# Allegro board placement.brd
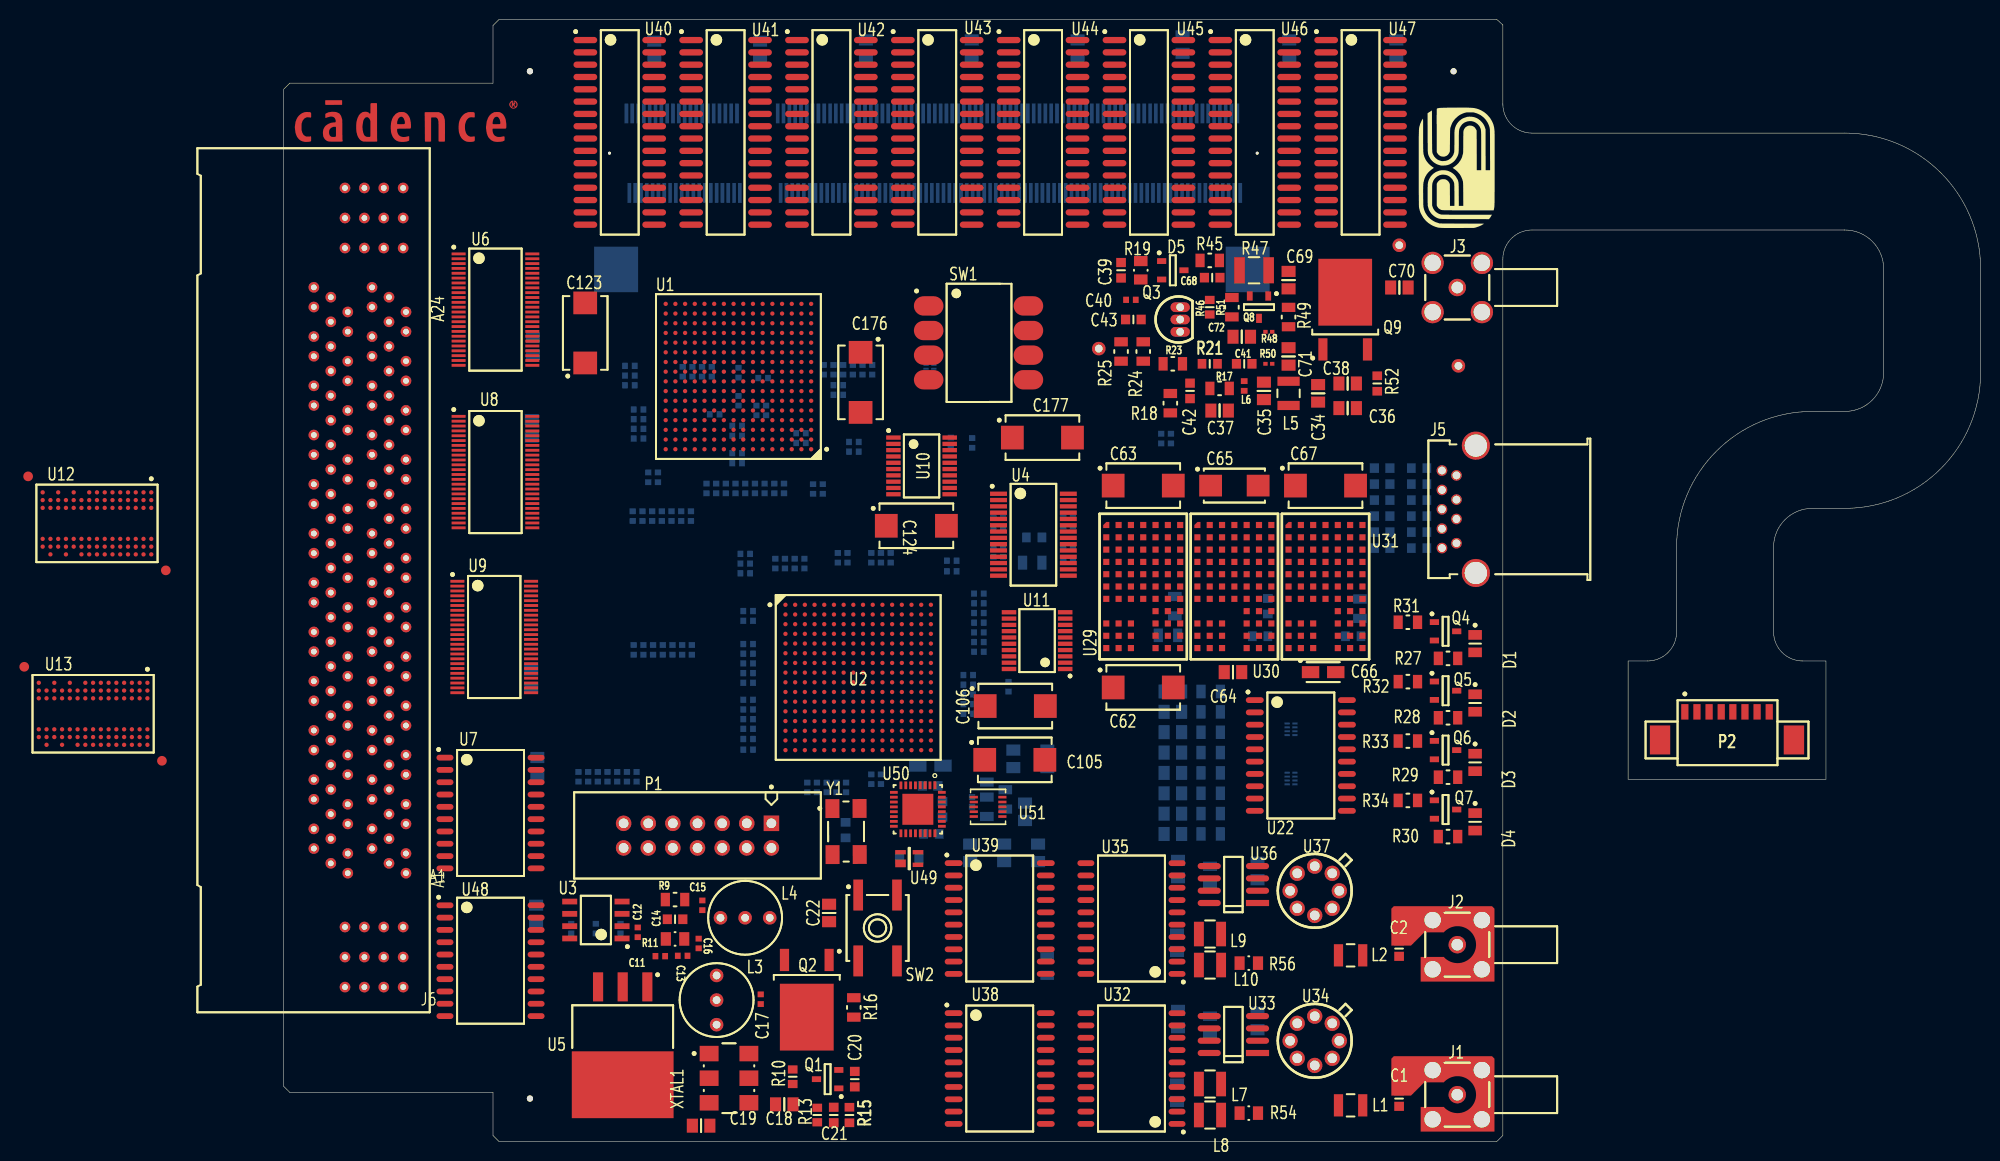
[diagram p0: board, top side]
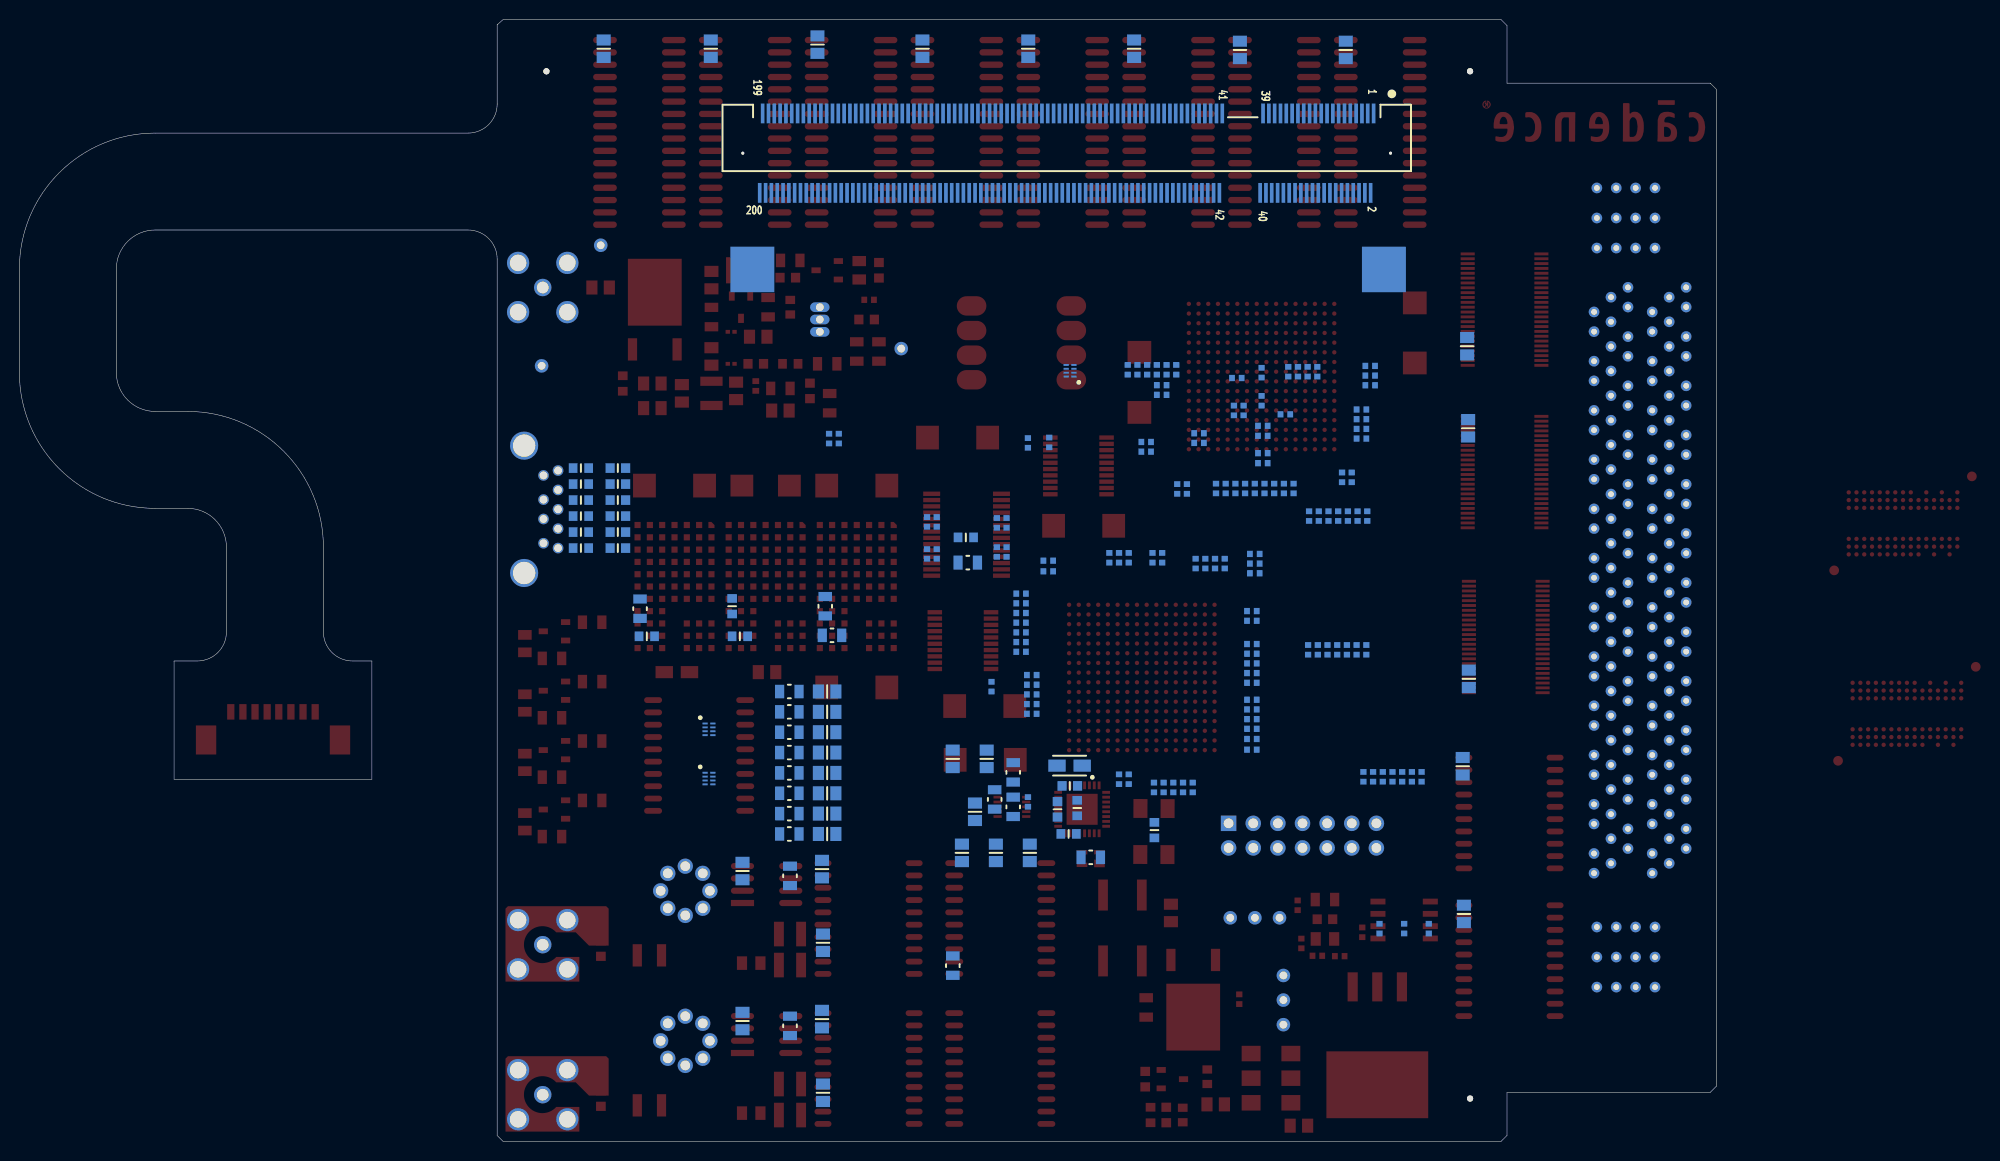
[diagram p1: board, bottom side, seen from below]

Outline 175 x 115.8 mm; copper layers: TOP, GND, INNER1, INNER2, POWER, BOTTOM. Coordinates in mm from the lower left corner of the outline.
Outline path: 0,108.59 0,5.71 0.63,5.08 21.59,5.08 21.59,0.64 22.22,0 125.09,0 125.73,0.64 125.73,91.07 arc(126.61,93.19) 128.73,94.07 161,94.07 arc(163.83,92.9) 165,90.07 165,79.34 arc(163.83,76.52) 161,75.34 157.65,75.34 arc(147.75,71.24) 143.65,61.34 143.65,52.59 arc(142.77,50.47) 140.65,49.59 138.65,49.59 138.65,37.4 159.05,37.4 159.05,49.59 156.65,49.59 arc(154.53,50.47) 153.65,52.59 153.65,61.34 arc(154.82,64.17) 157.65,65.34 161,65.34 arc(170.9,69.45) 175,79.34 175,90.07 arc(170.9,99.97) 161,104.07 128.73,104.07 arc(126.61,104.95) 125.73,107.07 125.73,115.24 125.09,115.8 22.22,115.8 21.59,115.16 21.59,109.22 0.63,109.22 0,108.59

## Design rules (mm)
constraint set DEFAULT: 
net group CLOCK: nets CLOCK+ CLOCK-
net group D: nets D+ D-
net group DP1: nets DIFF1+ DIFF1-
net group DP_DATA0: nets DATA0+ DATA0-
net group DP_DATA1: nets DATA1+ DATA1-
net group DP_DATA2: nets DATA2+ DATA2-
net group DP_DATA3: nets DATA3+ DATA3-
net group STDA_SSRX: nets STDA_SSRX+ STDA_SSRX-
net group STDA_SSTX: nets STDA_SSTX+ STDA_SSTX-
net group ADDRESS: nets A0 A1 A2 A3 A4 A5 A6 A7 A8 A9 A10 A11 A12 A13 A14 A15 A16 A17 A18 A19 A20 A21 A22 A23
net group DATA: nets D0 D1 D2 D3 D4 D5 D6 D7 D9 D10 D11 D12 D13 D14 D15
net group DATA1[0..9]: nets DATA1.CLKA DATA1.VD0 DATA1.VD1 DATA1.VD2 DATA1.VD3 DATA1.VD4 DATA1.VD5 DATA1.VD6 DATA1.VD7 DATA1.WSTAT_L
net group DATA[0..20]: nets DATA.BA0 DATA.BA1 DATA.BA2 DATA.BA3 DATA.BD0 DATA.BD1 DATA.BD2 DATA.BD3 DATA.BD4 DATA.BD5 DATA.BD6 DATA.BD7 DATA.BD8 DATA.BD9 DATA.BD12 DATA.BD13 DATA.BD14 DATA.BD15 DATA.CLKB
net group DDS[0..10]: nets DDS.DATA0 DDS.DATA1 DDS.DATA2 DDS.DATA3 DDS.DATA4 DDS.DATA5 DDS.DATA6 DDS.DATA7 DDS.FQUD DDS.RESET DDS.WCLK
net group DQ: nets DDR_DQ0 DDR_DQ1 DDR_DQ2 DDR_DQ3 DDR_DQ4 DDR_DQ5 DDR_DQ6 DDR_DQ7 DDR_DQ8 DDR_DQ9 DDR_DQ10 DDR_DQ11 DDR_DQ12 DDR_DQ13 DDR_DQ14 DDR_DQ15 DDR_DQ16 DDR_DQ17 DDR_DQ18 DDR_DQ19 DDR_DQ20 DDR_DQ21 DDR_DQ22 DDR_DQ23 DDR_DQ24 DDR_DQ25 DDR_DQ26 DDR_DQ27 DDR_DQ28 DDR_DQ29 DDR_DQ30 DDR_DQ31
net group MEMORY[0..29]: nets MEMORY.CTRL.RCS0 MEMORY.CTRL.RCS1 MEMORY.CTRL.RCS2 MEMORY.CTRL.RCS3 MEMORY.CTRL.RWE MEMORY.RA0 MEMORY.RA1 MEMORY.RA2 MEMORY.RA3 MEMORY.RA4 MEMORY.RA5 MEMORY.RA6 MEMORY.RA7 MEMORY.RA8 MEMORY.RA9 MEMORY.RA10 MEMORY.RA11 MEMORY.RA12 MEMORY.RA13 MEMORY.RA14 MEMORY.RA15 MEMORY.RA16 MEMORY.RD0 MEMORY.RD1 MEMORY.RD2 MEMORY.RD3 MEMORY.RD4 MEMORY.RD5 MEMORY.RD6 MEMORY.RD7
net group POWER_GROUP: nets 0 1V2 1V8 2V5 3V3 5V GND EARTH V12N V+12 VCC
net group RF: nets BUF_OUT CENTER-TAP DDS_OUT LPF_OUT N00286 N00395 N61996 N62056 N62230 N62316 N62436 N62564 N68133 N70364 N80550 N81780 N277989 N884986 N2993541 Q1E Q2E
net group STEVE: nets N830942
net group STEVE_PH: nets VDX0 VDX1 VDX2 VDX3 VDX4 VDX5 VDX6 VDX7

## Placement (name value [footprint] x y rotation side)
C1  47 pF  [CAPC1608X86N]  115.03 4.44 90 top
C2  47 pF  [CAPC1608X86N]  115.03 19.92 90 top
C3  3300 pF  [CAPC2012X71N]  91.7 46.45 180 bottom
C4  3300 pF  [CAPC2012X71N]  91.7 38.05 180 bottom
C5  3300 pF  [CAPC2012X71N]  91.7 44.34 180 bottom
C6  3300 pF  [CAPC2012X71N]  91.7 35.95 180 bottom
C7  3300 pF  [CAPC2012X71N]  91.7 42.24 180 bottom
C8  3300 pF  [CAPC2012X71N]  91.7 33.84 180 bottom
C9  3300 pF  [CAPC2012X71N]  91.7 40.15 180 bottom
C10  3300 pF  [CAPC2012X71N]  91.7 31.75 180 bottom
C11  1000 pF  [CAPC1005X56N]  38.84 19.14 0 top
C12  1000 pF  [CAPC1005X56N]  36.52 21.6 270 top
C13  1000 pF  [CAPC1005X56N]  41.15 19.18 180 top
C14  0.01 uF  [CAPC1608X86N]  40.36 22.95 180 top
C15  1000 pF  [CAPC1005X56N]  43.18 24.38 90 top
C16  1000 pF  [CAPC1005X56N]  42.8 20.45 90 top
C17  1000 pF  [CAPC1005X56N]  49.2 14.7 270 top
C18  100 pF  [CAPC2012X70N]  51.63 3.85 180 top
C19  22 pF  [CAPC2012X71N]  43.05 1.65 0 top
C20  47 pF  [CAPC1608X86N]  58.9 6.45 90 top
C21  47 pF  [CAPC1608X86N]  56.73 2.75 90 top
C22  22 pF  [CAPC2012X71N]  56.25 23.59 270 top
C23  1000 pF  [CAPC1005X56N]  73.2 60.84 90 bottom
C24  1000 pF  [CAPC1005X56N]  81.4 60.65 90 bottom
C25  1000 pF  [CAPC1005X56N]  74.2 60.84 90 bottom
C26  1000 pF  [CAPC1005X56N]  80.4 60.65 90 bottom
C27  1000 pF  [CAPC1005X56N]  73.2 63.84 90 bottom
C28  1000 pF  [CAPC1005X56N]  80.4 63.95 90 bottom
C29  1000 pF  [CAPC1005X56N]  81.4 63.95 90 bottom
C30  1000 pF  [CAPC1005X56N]  74.2 63.84 90 bottom
C31  1000 pF  [CAPC1005X56N]  34.74 21.98 270 bottom
C32  1000 pF  [CAPC1005X56N]  32.2 21.98 270 bottom
C33  1000 pF  [CAPC1005X56N]  29.66 21.98 270 bottom
C34  3.3 pF  [CAPC2012X88N]  106.68 77.21 270 top
C35  8.2 pF  [CAPC2012X140N]  101.09 77.47 270 top
C36  22 pF  [CAPC2012X71N]  109.73 75.69 180 top
C37  22 pF  [CAPC2012X71N]  96.52 75.43 0 top
C38  33 pF  [CAPC2012X71N]  109.73 78.23 0 top
C39  0.01 uF  [CAPC1608X86N]  86.36 89.91 90 top
C40  1000 pF  [CAPC1005X56N]  87.38 86.86 0 top
C41  0.01 uF  [CAPC1608X86N]  99.06 80.26 0 top
C42  0.01 uF  [CAPC1608X86N]  93.47 77.47 90 top
C43  0.01 uF  [CAPC1608X86N]  87.63 84.83 0 top
C44  0.1 uF  [CAPC2012X100N]  25.53 47.75 270 bottom
C45  0.1 uF  [CAPC2012X100N]  26.16 38.73 270 bottom
C46  0.1 uF  [CAPC2012X100N]  25.6 73.61 90 bottom
C47  0.1 uF  [CAPC2012X100N]  25.7 82.07 270 bottom
C48  0.1 uF  [CAPC2012X100N]  92.7 113.19 270 bottom
C49  0.1 uF  [CAPC2012X100N]  49.13 112.65 270 bottom
C50  0.1 uF  [CAPC2012X100N]  103.7 112.78 270 bottom
C51  0.1 uF  [CAPC2012X100N]  60.05 112.78 270 bottom
C52  0.1 uF  [CAPC2012X100N]  81.88 112.78 270 bottom
C53  0.1 uF  [CAPC2012X100N]  38.22 112.65 270 bottom
C54  0.1 uF  [CAPC2012X100N]  70.96 112.78 270 bottom
C55  0.1 uF  [CAPC2012X100N]  114.74 112.78 270 bottom
C62  10 uF  [CAPMP7343X310N]  88.65 46.86 0 top
C63  100 uF  [CAPMP7343X310N]  88.65 67.69 0 top
C64  2.2 uF  [CAPC2012X71N]  97.9 48.45 0 top
C65  47 uF  [CAPMP6032X280N]  98.04 67.69 0 top
C66  4.7 uF  [CAPMP3216X180N]  107.2 48.45 0 top
C67  100 uF  [CAPMP7343X310N]  107.44 67.69 0 top
C68  0.01 uF  [CAPC1608X86N]  95.76 89.15 0 top
C69  0.47 uF  [CAPC2012X71N]  103.63 88.9 270 top
C70  0.47 uF  [CAPC2012X71N]  115.06 88.13 0 top
C71  0.47 uF  [CAPC2012X71N]  103.63 81.02 90 top
C72  0.01 uF  [CAPC2012X71N]  98.81 83.05 0 top
C73  22 pF  [CAPC1005X56N]  32.4 37.65 270 bottom
C74  22 pF  [CAPC1005X56N]  31.4 37.65 270 bottom
C75  22 pF  [CAPC1005X56N]  30.4 37.65 270 bottom
C76  22 pF  [CAPC1005X56N]  42.1 50.74 90 bottom
C77  22 pF  [CAPC1005X56N]  36.1 50.74 90 bottom
C78  22 pF  [CAPC1005X56N]  37.1 50.74 90 bottom
C79  22 pF  [CAPC1005X56N]  38.1 50.74 90 bottom
C80  22 pF  [CAPC1005X56N]  39.1 50.74 90 bottom
C81  220 pF  [CAPC1005X56N]  42 64.55 90 bottom
C82  220 pF  [CAPC1005X56N]  38 64.55 90 bottom
C83  220 pF  [CAPC1005X56N]  39 64.55 90 bottom
C84  220 pF  [CAPC1005X56N]  40 64.55 90 bottom
C85  2200 pF  [CAPC1005X56N]  47.9 47.34 180 bottom
C86  2200 pF  [CAPC1005X56N]  53.7 59.65 270 bottom
C87  2200 pF  [CAPC1005X56N]  51.7 59.65 270 bottom
C88  2200 pF  [CAPC1005X56N]  52.7 59.65 270 bottom
C89  22 pF  [CAPC1005X56N]  61.6 60.24 90 bottom
C90  22 pF  [CAPC1005X56N]  62.6 60.24 90 bottom
C91  22 pF  [CAPC1005X56N]  35.7 78.04 180 bottom
C92  22 pF  [CAPC1005X56N]  53.35 72.09 180 bottom
C93  22 pF  [CAPC1005X56N]  53.35 73.09 180 bottom
C94  22 pF  [CAPC1005X56N]  44.45 75.04 0 bottom
C95  22 pF  [CAPC1005X56N]  35.7 79.04 180 bottom
C96  22 pF  [CAPC1005X56N]  41.15 79.44 270 bottom
C97  22 pF  [CAPC1005X56N]  47.6 67.4 270 bottom
C98  22 pF  [CAPC1005X56N]  48.6 67.4 270 bottom
C99  220 pF  [CAPC1005X56N]  55 36.55 270 bottom
C100  220 pF  [CAPC1005X56N]  91.5 72.54 270 bottom
C101  220 pF  [CAPC1005X56N]  43.6 67.4 270 bottom
C102  220 pF  [CAPC1005X56N]  44.6 67.4 270 bottom
C103  220 pF  [CAPC1005X56N]  45.6 67.4 270 bottom
C104  220 pF  [CAPC1005X56N]  46.6 67.4 270 bottom
C105  470 uF  [CAPMP7343X430N]  75.4 39.4 0 top
C106  470 uF  [CAPMP7343X430N]  75.45 44.95 0 top
C107  22 pF  [CAPC1005X56N]  46.77 72.83 0 bottom
C108  22 pF  [CAPC1005X56N]  71 72.09 90 bottom
C109  22 pF  [CAPC1005X56N]  59.7 79.65 90 bottom
C110  22 pF  [CAPC1005X56N]  57.7 79.65 90 bottom
C111  22 pF  [CAPC1005X56N]  56.7 79.65 90 bottom
C112  220 pF  [CAPC1005X56N]  36.6 72.54 0 bottom
C113  220 pF  [CAPC1005X56N]  46.77 73.86 0 bottom
C114  220 pF  [CAPC1005X56N]  71.7 55.55 0 bottom
C115  2200 pF  [CAPC1005X56N]  71.7 53.55 0 bottom
C116  2200 pF  [CAPC1005X56N]  49.6 67.4 270 bottom
C117  220 pF  [CAPC1005X56N]  55.7 79.65 270 bottom
C118  220 pF  [CAPC1005X56N]  44.15 79.44 270 bottom
C119  220 pF  [CAPC1005X56N]  50.6 67.4 270 bottom
C120  2200 pF  [CAPC1005X56N]  42.15 79.44 270 bottom
C121  2200 pF  [CAPC1005X56N]  43.15 79.44 270 bottom
C122  2200 pF  [CAPC1005X56N]  49.75 75.44 270 bottom
C123  470 uF  [CAPMP7343X430N]  31.1 83.44 90 top
C124  470 uF  [CAPMP7343X430N]  65.25 63.55 0 top
C125  22 pF  [CAPC1005X56N]  47.9 54.74 180 bottom
C126  22 pF  [CAPC1005X56N]  47.9 53.74 180 bottom
C127  22 pF  [CAPC1005X56N]  46.9 76.44 270 bottom
C128  22 pF  [CAPC1005X56N]  46.9 79.34 270 bottom
C129  22 pF  [CAPC1005X56N]  57.2 78.06 0 bottom
C130  220 pF  [CAPC1005X56N]  55.6 67.34 270 bottom
C131  220 pF  [CAPC1005X56N]  54.6 67.34 270 bottom
C132  220 pF  [CAPC1005X56N]  37.6 68.54 270 bottom
C133  2200 pF  [CAPC1005X56N]  71.7 52.55 0 bottom
C134  22 pF  [CAPC1005X56N]  47.9 42.59 180 bottom
C135  22 pF  [CAPC1005X56N]  47.9 50.34 180 bottom
C136  22 pF  [CAPC1005X56N]  47.9 49.34 180 bottom
C137  22 pF  [CAPC1005X56N]  47.9 44.59 180 bottom
C138  22 pF  [CAPC1005X56N]  47.9 43.59 180 bottom
C139  22 pF  [CAPC1005X56N]  41 64.55 90 bottom
C140  220 pF  [CAPC1005X56N]  71.7 56.55 0 bottom
C141  220 pF  [CAPC1005X56N]  71.7 50.55 0 bottom
C142  2200 pF  [CAPC1005X56N]  47.9 51.34 180 bottom
C143  2200 pF  [CAPC1005X56N]  47.9 48.34 180 bottom
C144  22 pF  [CAPC1005X56N]  54 36.55 270 bottom
C145  22 pF  [CAPC1005X56N]  70.6 44.15 0 bottom
C146  22 pF  [CAPC1005X56N]  47.6 60.65 180 bottom
C147  22 pF  [CAPC1005X56N]  48.75 75.44 270 bottom
C148  22 pF  [CAPC1005X56N]  90.5 72.54 270 bottom
C149  22 pF  [CAPC1005X56N]  68.8 72.15 270 bottom
C150  22 pF  [CAPC1005X56N]  74.75 46.95 270 bottom
C151  22 pF  [CAPC1005X56N]  49.45 78.79 180 bottom
C152  22 pF  [CAPC1005X56N]  35.7 80.04 180 bottom
C153  22 pF  [CAPC1005X56N]  51.6 67.4 270 bottom
C154  220 pF  [CAPC1005X56N]  70.6 47.15 0 bottom
C155  220 pF  [CAPC1005X56N]  70.6 46.15 0 bottom
C156  220 pF  [CAPC1005X56N]  47.6 58.65 180 bottom
C157  220 pF  [CAPC1005X56N]  70.6 45.15 0 bottom
C158  220 pF  [CAPC1005X56N]  58.15 60.24 90 bottom
C159  220 pF  [CAPC1005X56N]  60.6 60.24 90 bottom
C160  22 pF  [CAPC1005X56N]  36.6 74.54 0 bottom
C161  22 pF  [CAPC1005X56N]  46.77 71.04 0 bottom
C162  22 pF  [CAPC1005X56N]  58.7 79.65 90 bottom
C163  22 pF  [CAPC1005X56N]  36.6 75.54 0 bottom
C164  22 pF  [CAPC1005X56N]  46.77 70.01 0 bottom
C165  220 pF  [CAPC1005X56N]  58.8 72.19 0 bottom
C166  220 pF  [CAPC1005X56N]  58.8 71.19 0 bottom
C167  220 pF  [CAPC1005X56N]  36.6 73.54 0 bottom
C168  2200 pF  [CAPC1005X56N]  71.7 54.55 0 bottom
C169  2200 pF  [CAPC1005X56N]  60.7 79.65 90 bottom
C170  220 pF  [CAPC1005X56N]  56 36.55 270 bottom
C171  220 pF  [CAPC1005X56N]  47.6 59.65 180 bottom
C172  220 pF  [CAPC1005X56N]  57.15 60.24 90 bottom
C173  2200 pF  [CAPC1005X56N]  70.6 48.15 0 bottom
C174  2200 pF  [CAPC1005X56N]  58 36.55 270 bottom
C175  2200 pF  [CAPC1005X56N]  57 36.55 270 bottom
C176  470 uF  [CAPMP7343X430N]  59.5 78.34 270 top
C177  470 uF  [CAPMP7343X430N]  78.25 72.65 0 top
C178  22 pF  [CAPC1005X56N]  60.6 37.4 270 bottom
C179  22 pF  [CAPC1005X56N]  47.9 41.55 180 bottom
C180  22 pF  [CAPC1005X56N]  47.9 40.45 180 bottom
C181  22 pF  [CAPC1005X56N]  68.9 58.84 180 bottom
C182  22 pF  [CAPC1005X56N]  68.9 59.95 180 bottom
C183  220 pF  [CAPC1005X56N]  57.2 77.06 0 bottom
C184  220 pF  [CAPC1005X56N]  38.6 68.54 270 bottom
C185  220 pF  [CAPC1005X56N]  61.6 37.4 270 bottom
C186  2200 pF  [CAPC1005X56N]  71.7 51.55 0 bottom
C187  22 pF  [CAPC1005X56N]  36.4 37.65 270 bottom
C188  22 pF  [CAPC1005X56N]  40.1 50.74 90 bottom
C189  22 pF  [CAPC1005X56N]  34.4 37.65 270 bottom
C190  22 pF  [CAPC1005X56N]  33.4 37.65 270 bottom
C191  22 pF  [CAPC1005X56N]  41.1 50.74 90 bottom
C192  22 pF  [CAPC1005X56N]  35.4 37.65 270 bottom
C193  220 pF  [CAPC1005X56N]  36 64.55 90 bottom
C194  220 pF  [CAPC1005X56N]  37 64.55 90 bottom
C195  2200 pF  [CAPC1005X56N]  50.7 59.65 270 bottom
C196  2200 pF  [CAPC1005X56N]  47.9 45.59 180 bottom
C197  0.1 uF  [CAPC2012X100N]  92.23 12.64 90 bottom
C198  0.1 uF  [CAPC2012X100N]  92.13 5.04 270 bottom
C199  0.1 uF  [CAPC2012X100N]  100.43 12.44 270 bottom
C200  0.1 uF  [CAPC2012X100N]  92.23 28.12 90 bottom
C201  0.1 uF  [CAPC2012X100N]  92.13 20.52 270 bottom
C202  0.1 uF  [CAPC2012X100N]  100.43 27.92 270 bottom
C2000  33 pF  [CAPC1608X86N]  113.28 66.2 180 bottom
C2001  33 pF  [CAPC1608X86N]  113.28 64.55 180 bottom
C2002  33 pF  [CAPC1608X86N]  113.28 67.85 180 bottom
C2003  33 pF  [CAPC1608X86N]  113.28 69.5 180 bottom
C2004  33 pF  [CAPC1608X86N]  113.28 61.25 180 bottom
C2005  33 pF  [CAPC1608X86N]  113.28 62.9 180 bottom
C2006  0.1 uF  [CAPC2012X100N]  26.04 23.5 270 bottom
C2007  0.01 uF  [CAPC1608X87N]  67.94 34.29 270 bottom
C2008  22 uF  [CAPMP3216X120N]  66.7 38.8 0 bottom
C2009  0.01 uF  [CAPC1608X87N]  66.67 36.7 0 bottom
C2010  1000 pF  [CAPC1005X56N]  70.99 35.05 270 bottom
C2011  0.1 uF  [CAPC2012X100N]  77.8 29.8 270 bottom
C2012  0.1 uF  [CAPC2012X100N]  74.3 29.8 270 bottom
C2013  0.1 uF  [CAPC2012X100N]  70.8 29.8 270 bottom
C2014  0.1 uF  [CAPC2012X100N]  78.75 39.49 270 bottom
C2015  0.1 uF  [CAPC2012X100N]  75.25 39.49 270 bottom
C2016  0.1 uF  [CAPC2012X100N]  76.45 34.04 90 bottom
D1  GREEN  [LEDC2012X120N]  122.87 51.39 270 top
D2  GREEN  [LEDC2012X120N]  122.87 45.26 270 top
D3  GREEN  [LEDC2012X120N]  122.87 39.13 270 top
D4  GREEN  [LEDC2012X120N]  122.87 33 270 top
D5  MMBD4148  [SOT95P230X109-3N]  91.69 89.91 0 top
J1  901-9894-RFX  [SMB_90]  121.03 4.84 270 top
J2  901-9894-RFX  [SMB_90]  121.03 20.32 270 top
J3  901-9894-RFX  [SMB_90]  121.03 88.13 270 top
J5  AU-Y1005-3-R  [USB3A_FEMALE]  119.45 65.25 90 top
J6  6367550-6  [C-1367550-6]  6.33 15.95 90 top
J7  1473005-1  [C_1_1473005_1_J1]  66.85 102 270 bottom
L1  47 nH  [INDC2520X220N]  110.03 3.74 0 top
L2  47 nH  [INDC2520X220N]  110.03 19.22 0 top
L3  INDUCTOR3  [TOROID01_3]  44.65 17.14 270 top
L4  INDUCTOR3  [TOROID01_3]  45.05 23.09 0 top
L5  1.0 uH  [INDC2520X220N]  103.63 77.21 90 top
L6  6.8 nH  [INDC1005X60N]  99.06 77.97 270 top
L7  56 nH  [IND_CENTRAL_1008]  95.53 5.94 180 top
L8  56 nH  [IND_CENTRAL_1008]  95.53 2.74 0 top
L9  56 nH  [IND_CENTRAL_1008]  95.53 21.42 180 top
L10  56 nH  [IND_CENTRAL_1008]  95.53 18.22 0 top
NOREF  -  []  25.4 4.45 0 top
NOREF#2  -  []  -0.13 102.24 0 top
NOREF#3  -  []  25.4 4.45 0 top
NOREF#4  -  [unnamed#2]  70.6 73.44 0 top
NOREF#5  -  [unnamed#3]  120.65 110.44 0 top
NOREF#6  -  [unnamed#3]  25.4 110.44 0 top
NOREF#7  -  [unnamed#3]  25.4 4.45 0 top
NOREF#8  -  []  125.1 94.15 90 top
P1  TST-107-01-G-D  [SAMTEC_TST-107-XX-X-D]  50.3 32.84 180 top
P2  53261-0819  [MOLEX_53261-8_FITNAIL]  148.85 41.45 0 top
Q1  2N2222AUB  [SOT95P230X109-3N]  56.1 6.45 180 top
Q2  MMBFJ310LT1G  [TO230P950X240-3N]  53.95 14.64 270 top
Q3  2N3866  [TO92]  92.46 83.56 180 top
Q4  KST3904  [SOT95P240X114-3N]  119.82 52.66 0 top
Q5  KST3904  [SOT95P240X114-3N]  119.82 46.53 0 top
Q6  KST3904  [SOT95P240X114-3N]  119.82 40.4 0 top
Q7  KST3904  [SOT95P240X114-3N]  119.82 34.27 0 top
Q8  2N3905  [SOT95P230X109-3N]  100.58 86.1 270 top
Q9  2N5179-NRC  [TO230P950X240-3N]  109.47 85.85 90 top
R1  47.5 Ohm  [RESC2012X60N]  95.6 46.45 0 bottom
R2  47.5 Ohm  [RESC2012X60N]  95.6 38.05 0 bottom
R3  47.5 Ohm  [RESC2012X60N]  95.6 44.34 0 bottom
R4  47.5 Ohm  [RESC2012X60N]  95.6 35.95 0 bottom
R5  47.5 Ohm  [RESC2012X60N]  95.6 42.24 0 bottom
R6  47.5 Ohm  [RESC2012X60N]  95.6 33.84 0 bottom
R7  47.5 Ohm  [RESC2012X60N]  95.6 40.15 0 bottom
R8  47.5 Ohm  [RESC2012X60N]  95.6 31.75 0 bottom
R9  330 Ohm  [RESC2012X60N]  40.36 24.98 180 top
R10  10 kOhm  [RESC1608X50N]  52.5 6.7 90 top
R11  97.6 Ohm  [RESC2012X70N]  40.36 20.91 0 top
R12  2.0 kOhm  [RESC1608X55N]  77.4 62.34 0 bottom
R13  10 kOhm  [RESC1608X50N]  55.03 2.75 90 top
R14  3.9 kOhm  [RESC2012X50N]  77.2 59.74 180 bottom
R15  2.0 kOhm  [RESC1608X55N]  58.35 2.75 90 top
R16  220 Ohm  [RESC2012X60N]  58.8 13.85 270 top
R17  180 Ohm  [RESC2012X60N]  96.52 77.72 180 top
R18  56 Ohm  [RESC2012X60N]  91.44 76.19 90 top
R19  97.6 Ohm  [RESC2012X70N]  88.39 89.91 90 top
R21  2.0 kOhm  [RESC1608X55N]  95.5 80.26 0 top
R23  470 Ohm  [RESC2012X60N]  91.69 80.26 0 top
R24  56 Ohm  [RESC2012X60N]  88.65 81.53 90 top
R25  56 Ohm  [RESC2012X60N]  86.36 81.53 90 top
R26  49.9 Ohm  [RESC2012X60N]  78.74 18.16 270 bottom
R27  470 Ohm  [RESC2012X60N]  120.08 49.86 0 top
R28  470 Ohm  [RESC2012X60N]  120.08 43.73 0 top
R29  470 Ohm  [RESC2012X60N]  120.08 37.6 0 top
R30  470 Ohm  [RESC2012X60N]  120.08 31.47 0 top
R31  150 Ohm  [RESC2012X60N]  115.94 53.59 0 top
R32  150 Ohm  [RESC2012X60N]  115.94 47.46 0 top
R33  150 Ohm  [RESC2012X60N]  115.94 41.33 0 top
R34  150 Ohm  [RESC2012X60N]  115.94 35.2 0 top
R39  105 kOhm  [RESC2012X60N]  91.9 55.24 270 bottom
R40  953 kOhm  [RESC2012X60N]  91.2 52.24 180 bottom
R41  61.9 kOhm  [RESC1608X55N]  101.5 55.24 270 bottom
R42  226 kOhm  [RESC1608X55N]  100.7 52.15 180 bottom
R43  118 kOhm  [RESC2012X60N]  111 54.99 270 bottom
R44  154 kOhm  [RESC1608X55N]  110.3 52.15 180 bottom
R45  470 Ohm  [RESC2012X60N]  95.5 90.93 180 top
R46  3.0 kOhm  [RESC1608X50N]  95.5 86.1 90 top
R47  270 Ohm  [RESC3225X70N]  100.08 89.91 180 top
R48  24 kOhm  [RESC0603X26N]  101.6 83.56 180 top
R49  470 Ohm  [RESC2012X60N]  103.63 85.09 90 top
R50  49.9 Ohm  [RESC0603X30N]  101.6 80.26 0 top
R51  6.8 kOhm  [RESC2012X60N]  97.79 86.1 90 top
R52  3.3 Ohm  [RESC1608X55N]  112.78 78.23 90 top
R53  97.6 Ohm  [RESC2012X50N]  95.53 11.94 270 bottom
R54  97.6 Ohm  [RESC2012X70N]  99.53 2.94 0 top
R55  97.6 Ohm  [RESC2012X50N]  95.53 27.42 270 bottom
R56  97.6 Ohm  [RESC2012X70N]  99.53 18.42 0 top
R2000  27.4 Ohm  [RESC1608X55N]  117.09 64.55 180 bottom
R2001  27.4 Ohm  [RESC1608X55N]  117.09 66.2 180 bottom
R2002  27.4 Ohm  [RESC1608X55N]  117.09 69.5 180 bottom
R2003  27.4 Ohm  [RESC1608X55N]  117.09 67.85 180 bottom
R2004  27.4 Ohm  [RESC1608X55N]  117.09 62.9 180 bottom
R2005  27.4 Ohm  [RESC1608X55N]  117.09 61.25 180 bottom
R2006  10  [RESC1608X55N]  65.91 34.42 90 bottom
R2007  2.0 kOhm  [RESC1608X55N]  66.8 31.75 0 bottom
R2008  100 kOhm  [RESC2012X60N]  64.52 29.34 180 bottom
R2009  2.0 kOhm  [RESC1608X55N]  57.95 32.14 90 bottom
R2010  10 kOhm  [RESC2012X60N]  72.52 38.1 270 bottom
R2011  10 kOhm  [RESC2012X60N]  72.52 34.54 270 bottom
R2012  100 kOhm  [RESC2012X60N]  74.42 35.31 270 bottom
RN1  100 Ohm  [RESNET_8]  66.65 79.54 0 bottom
RN2  100 Ohm  [RESNET_8]  103.89 37.47 180 bottom
RN3  100 Ohm  [RESNET_8]  103.89 42.55 180 bottom
SW1  76HPSB04GWRT  [SOIC254P1077X800-8M]  71.12 82.42 0 top
SW2  EVQPH  [SW_EVQ-PH_NO_GND]  61.25 22.05 0 top
U1  XC6SLX25-3FTG256  [FT256]  46.9 78.94 180 top
U2  XC6SLX25-3FTG256  [FT256]  59.25 47.9 0 top
U3  L78L08ACD13TR  [SOIC127P600X175-8N]  32.2 22.87 180 top
U4  AD9850BRSZ  [SOP65P780X200-28N]  77.32 62.62 0 top
U5  LM340  [TO254P1410X464-4N]  34.97 9.97 270 top
U6  74ALVT16245DGG,118  [SOP50P810X110-48N]  21.84 85.85 0 top
U7  74ACT245  [SOIC127P1028X265-20N]  21.34 33.91 0 top
U8  74ALVT16245DGG,118  [SOP50P810X110-48N]  21.84 69.09 0 top
U9  74ALVT16245DGG,118  [SOP50P810X110-48N]  21.72 52.07 0 top
U10  XCF01SVOG20C  [XCF01SVOG20]  65.79 69.72 0 top
U11  XCF01SVOG20C  [XCF01SVOG20]  77.7 51.7 180 top
U12  MT47H64M16HR-3:G TR  [MT47H128M]  -19.25 63.8 270 top
U13  MT47H64M16HR-3:G TR  [MT47H128M]  -19.65 44.15 270 top
U22  74HCT574  [SOIC127P1032X265-20AN]  104.9 39.84 0 top
U29  LTM8025EV#PBF  [LTUMODULE7X11]  88.65 57.28 0 top
U30  LTM8025EV#PBF  [LTUMODULE7X11]  98.04 57.28 0 top
U31  LTM8025EV#PBF  [LTUMODULE7X11]  107.44 57.28 0 top
U32  TLC5602CDWR  [SOIC127P1028X265-20N]  87.43 7.54 180 top
U33  DG419CY+  [SOG0508WG244L225]  100.43 9.14 90 top
U34  TLE2037AQDRG4Q1  [TO99]  106.33 12.94 180 top
U35  TLC5602CDWR  [SOIC127P1028X265-20N]  87.43 23.02 180 top
U36  DG419CY+  [SOG0508WG244L225]  100.43 24.62 90 top
U37  TLE2037AQDRG4Q1  [TO99]  106.33 28.42 180 top
U38  74HCT574  [SOIC127P1032X265-20AN]  73.84 7.54 0 top
U39  74HCT574  [SOIC127P1032X265-20AN]  73.84 23.02 0 top
U40  UPD431000AGW-B15  [SOJ127P866X375-32N]  34.66 104.14 0 top
U41  UPD431000AGW-B15  [SOJ127P866X375-32N]  45.58 104.14 0 top
U42  UPD431000AGW-B15  [SOJ127P866X375-32N]  56.49 104.14 0 top
U43  UPD431000AGW-B15  [SOJ127P866X375-32N]  67.41 104.14 0 top
U44  UPD431000AGW-B15  [SOJ127P866X375-32N]  78.32 104.14 0 top
U45  UPD431000AGW-B15  [SOJ127P866X375-32N]  89.23 104.14 0 top
U46  UPD431000AGW-B15  [SOJ127P866X375-32N]  100.15 104.14 0 top
U47  UPD431000AGW-B15  [SOJ127P866X375-32N]  111.06 104.14 0 top
U48  74ACT245  [SOIC127P1028X265-20N]  21.34 18.67 0 top
U49  MAX6711S  [SOT343N]  64.52 29.21 0 top
U50  NBC12429AMNR4G  [QFN50P500X500X100-33N]  65.41 34.29 270 top
U51  TPS51200DRCR  [DRC10_2P4X1P65]  72.64 34.54 0 top
XTAL1  100 MHz  [OSCSC254P500X700X200-6N]  45.93 6.54 0 top
Y1  20 MHz  [OSCCC350X600X120N]  58 32 0.2 top

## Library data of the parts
C1 C197-C199 = CAP: room: CHAN1
C2 C200-C202 = CAP: room: CHAN2
C3-C33 C44-C47 C64 C73-C104 C107-C122 C125-C175 C178-C196 C2000-C2007 C2009-C2016 = CAP
C34-C43 C68-C72 = CAP: room: RF-AMP
C48-C55 = CAP: room: BOTTOM_MEM
C62 C63 C65-C67 C105 C106 C123 C124 C176 C177 C2008 = CAP_P
D1-D4 = LED
D5 = DIODE_A_NC_C: room: RF-AMP
J1 = BNC-4: User Part Number: PSL-00000003; room: CHAN1
J2 = BNC-4: User Part Number: PSL-00000003; room: CHAN2
J3 = BNC-4: User Part Number: PSL-00000003
J5 = usb3a_female: User Part Number: PSL-00000013
J6 = CONN_C1367550_6
J7 = conn_dimm_200: room: BOTTOM_MEM
L1 L7 L8 = IND: room: CHAN1
L2 L9 L10 = IND: room: CHAN2
L3 L4 = INDUCTOR3
L5 L6 = IND: room: RF-AMP
P1 = HDR_2X7_M
P2 = HDR_1X8_M
Q1 Q4-Q7 = BJT_NPN_BEC
Q2 = MOSFET_I_EN_GSD
Q3 Q9 = BJT_NPN_BEC: room: RF-AMP
Q8 = BJT_PNP_BCE: room: RF-AMP
R1-R16 R26-R34 R39-R44 R2000-R2012 = RES
R17-R19 R21 R23-R25 R45-R52 = RES: room: RF-AMP
R53 R54 = RES: room: CHAN1
R55 R56 = RES: room: CHAN2
RN1-RN3 = RES_net_8
SW1 = SW DIP-4/SM
SW2 = SW_SPST_13_24
U1 = DemoG_Interface
U2 = DemoG_CoProc
U3 = LM78L05_SO8
U4 = AD9850
U5 = VREG_TGND
U6 U8 U9 = FCT16245
U7 U48 = 74-245_20P
U10 U11 = xcf01svog20
U12 U13 = MT47H64M16
U22 U38 U39 = FF_D_8X_OE3S_20P: User Part Number: EMA-00007307V22
U29-U31 = LTM8025
U32 = TLC5602A: room: CHAN1
U33 = DG419A: room: CHAN1
U34 = TLE2037A: room: CHAN1
U35 = TLC5602A: room: CHAN2
U36 = DG419A: room: CHAN2
U37 = TLE2037A: room: CHAN2
U40-U47 = UPD431000AGW-B15: room: MEM
U49 = MAX6711
U50 = NBC12429
U51 = TPS51200
XTAL1 = OSC_SEL383
Y1 = OSC4_24NC

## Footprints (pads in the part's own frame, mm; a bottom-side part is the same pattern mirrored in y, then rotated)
C-1367550-6
  round 1.1 hole 0.6: (0,0) (0,-2) (0,-4) (0,-6) (3.1,0) (3.1,-2) (3.1,-4) (3.1,-6) (6.2,0) (6.2,-2) (6.2,-4) (6.2,-6) (76.26,0) (76.26,-2) (76.26,-4) (76.26,-6) (79.36,0) (79.36,-2) (79.36,-4) (79.36,-6) (82.46,0) (82.46,-2) (82.46,-4) (82.46,-6) A1(11.755,-6.29) A2(13.785,-6.29) A3(16.835,-6.29) A4(18.865,-6.29) A5(21.915,-6.29) A6(23.945,-6.29) A7(26.995,-6.29) A8(29.025,-6.29) A9(32.075,-6.29) A10(34.105,-6.29) A11(37.155,-6.29) A12(39.185,-6.29) A13(42.235,-6.29) A14(44.265,-6.29) A15(47.315,-6.29) A16(49.345,-6.29) A17(52.395,-6.29) A18(54.425,-6.29) A19(57.475,-6.29) A20(59.505,-6.29) A21(62.555,-6.29) A22(64.585,-6.29) A23(67.635,-6.29) A24(69.665,-6.29) B1(12.77,-4.54) B2(15.31,-4.54) B3(17.85,-4.54) B4(20.39,-4.54) B5(22.93,-4.54) B6(25.47,-4.54) B7(28.01,-4.54) B8(30.55,-4.54) B9(33.09,-4.54) B10(35.63,-4.54) B11(38.17,-4.54) B12(40.71,-4.54) B13(43.25,-4.54) B14(45.79,-4.54) B15(48.33,-4.54) B16(50.87,-4.54) B17(53.41,-4.54) B18(55.95,-4.54) B19(58.49,-4.54) B20(61.03,-4.54) B21(63.57,-4.54) B22(66.11,-4.54) B23(68.65,-4.54) B24(71.19,-4.54) C1(14.295,-2.79) C2(16.325,-2.79) C3(19.375,-2.79) C4(21.405,-2.79) C5(24.455,-2.79) C6(26.485,-2.79) C7(29.535,-2.79) C8(31.565,-2.79) C9(34.615,-2.79) C10(36.645,-2.79) C11(39.695,-2.79) C12(41.725,-2.79) C13(44.775,-2.79) C14(46.805,-2.79) C15(49.855,-2.79) C16(51.885,-2.79) C17(54.935,-2.79) C18(56.965,-2.79) C19(60.015,-2.79) C20(62.045,-2.79) C21(65.095,-2.79) C22(67.125,-2.79) C23(70.175,-2.79) C24(72.205,-2.79) D1(11.755,-0.29) D2(13.785,-0.29) D3(16.835,-0.29) D4(18.865,-0.29) D5(21.915,-0.29) D6(23.945,-0.29) D7(26.995,-0.29) D8(29.025,-0.29) D9(32.075,-0.29) D10(34.105,-0.29) D11(37.155,-0.29) D12(39.185,-0.29) D13(42.235,-0.29) D14(44.265,-0.29) D15(47.315,-0.29) D16(49.345,-0.29) D17(52.395,-0.29) D18(54.425,-0.29) D19(57.475,-0.29) D20(59.505,-0.29) D21(62.555,-0.29) D22(64.585,-0.29) D23(67.635,-0.29) D24(69.665,-0.29) E1(12.77,1.46) E2(15.31,1.46) E3(17.85,1.46) E4(20.39,1.46) E5(22.93,1.46) E6(25.47,1.46) E7(28.01,1.46) E8(30.55,1.46) E9(33.09,1.46) E10(35.63,1.46) E11(38.17,1.46) E12(40.71,1.46) E13(43.25,1.46) E14(45.79,1.46) E15(48.33,1.46) E16(50.87,1.46) E17(53.41,1.46) E18(55.95,1.46) E19(58.49,1.46) E20(61.03,1.46) E21(63.57,1.46) E22(66.11,1.46) E23(68.65,1.46) E24(71.19,1.46) F1(14.295,3.21) F2(16.325,3.21) F3(19.375,3.21) F4(21.405,3.21) F5(24.455,3.21) F6(26.485,3.21) F7(29.535,3.21) F8(31.565,3.21) F9(34.615,3.21) F10(36.645,3.21) F11(39.695,3.21) F12(41.725,3.21) F13(44.775,3.21) F14(46.805,3.21) F15(49.855,3.21) F16(51.885,3.21) F17(54.935,3.21) F18(56.965,3.21) F19(60.015,3.21) F20(62.045,3.21) F21(65.095,3.21) F22(67.125,3.21) F23(70.175,3.21) F24(72.205,3.21)
C_1_1473005_1_J1
  round 0.3 hole 1.1 unplated: (0,-33.55) (0,33.25)
  rect 4.7x4.53 smd: (12,-32.565) (12,32.565)
  rect 2.05x0.38 smd: 1(-4.1,31.5) 2(4.1,31.2) 3(-4.1,30.9) 4(4.1,30.6) 5(-4.1,30.3) 6(4.1,30) 7(-4.1,29.7) 8(4.1,29.4) 9(-4.1,29.1) 10(4.1,28.8) 11(-4.1,28.5) 12(4.1,28.2) 13(-4.1,27.9) 14(4.1,27.6) 15(-4.1,27.3) 16(4.1,27) 17(-4.1,26.7) 18(4.1,26.4) 19(-4.1,26.1) 20(4.1,25.8) 21(-4.1,25.5) 22(4.1,25.2) 23(-4.1,24.9) 24(4.1,24.6) 25(-4.1,24.3) 26(4.1,24) 27(-4.1,23.7) 28(4.1,23.4) 29(-4.1,23.1) 30(4.1,22.8) 31(-4.1,22.5) 32(4.1,22.2) 33(-4.1,21.9) 34(4.1,21.6) 35(-4.1,21.3) 36(4.1,21) 37(-4.1,20.7) 38(4.1,20.4) 39(-4.1,20.1) 40(4.1,19.8) 41(-4.1,15.9) 42(4.1,15.6) 43(-4.1,15.3) 44(4.1,15) 45(-4.1,14.7) 46(4.1,14.4) 47(-4.1,14.1) 48(4.1,13.8) 49(-4.1,13.5) 50(4.1,13.2) 51(-4.1,12.9) 52(4.1,12.6) 53(-4.1,12.3) 54(4.1,12) 55(-4.1,11.7) 56(4.1,11.4) 57(-4.1,11.1) 58(4.1,10.8) 59(-4.1,10.5) 60(4.1,10.2) 61(-4.1,9.9) 62(4.1,9.6) 63(-4.1,9.3) 64(4.1,9) 65(-4.1,8.7) 66(4.1,8.4) 67(-4.1,8.1) 68(4.1,7.8) 69(-4.1,7.5) 70(4.1,7.2) 71(-4.1,6.9) 72(4.1,6.6) 73(-4.1,6.3) 74(4.1,6) 75(-4.1,5.7) 76(4.1,5.4) 77(-4.1,5.1) 78(4.1,4.8) 79(-4.1,4.5) 80(4.1,4.2) 81(-4.1,3.9) 82(4.1,3.6) 83(-4.1,3.3) 84(4.1,3) 85(-4.1,2.7) 86(4.1,2.4) 87(-4.1,2.1) 88(4.1,1.8) 89(-4.1,1.5) 90(4.1,1.2) 91(-4.1,0.9) 92(4.1,0.6) 93(-4.1,0.3) 94(4.1,0) 95(-4.1,-0.3) 96(4.1,-0.6) 97(-4.1,-0.9) 98(4.1,-1.2) 99(-4.1,-1.5) 100(4.1,-1.8) 101(-4.1,-2.1) 102(4.1,-2.4) 103(-4.1,-2.7) 104(4.1,-3) 105(-4.1,-3.3) 106(4.1,-3.6) 107(-4.1,-3.9) 108(4.1,-4.2) 109(-4.1,-4.5) 110(4.1,-4.8) 111(-4.1,-5.1) 112(4.1,-5.4) 113(-4.1,-5.7) 114(4.1,-6) 115(-4.1,-6.3) 116(4.1,-6.6) 117(-4.1,-6.9) 118(4.1,-7.2) 119(-4.1,-7.5) 120(4.1,-7.8) 121(-4.1,-8.1) 122(4.1,-8.4) 123(-4.1,-8.7) 124(4.1,-9) 125(-4.1,-9.3) 126(4.1,-9.6) 127(-4.1,-9.9) 128(4.1,-10.2) 129(-4.1,-10.5) 130(4.1,-10.8) 131(-4.1,-11.1) 132(4.1,-11.4) 133(-4.1,-11.7) 134(4.1,-12) 135(-4.1,-12.3) 136(4.1,-12.6) 137(-4.1,-12.9) 138(4.1,-13.2) 139(-4.1,-13.5) 140(4.1,-13.8) 141(-4.1,-14.1) 142(4.1,-14.4) 143(-4.1,-14.7) 144(4.1,-15) 145(-4.1,-15.3) 146(4.1,-15.6) 147(-4.1,-15.9) 148(4.1,-16.2) 149(-4.1,-16.5) 150(4.1,-16.8) 151(-4.1,-17.1) 152(4.1,-17.4) 153(-4.1,-17.7) 154(4.1,-18) 155(-4.1,-18.3) 156(4.1,-18.6) 157(-4.1,-18.9) 158(4.1,-19.2) 159(-4.1,-19.5) 160(4.1,-19.8) 161(-4.1,-20.1) 162(4.1,-20.4) 163(-4.1,-20.7) 164(4.1,-21) 165(-4.1,-21.3) 166(4.1,-21.6) 167(-4.1,-21.9) 168(4.1,-22.2) 169(-4.1,-22.5) 170(4.1,-22.8) 171(-4.1,-23.1) 172(4.1,-23.4) 173(-4.1,-23.7) 174(4.1,-24) 175(-4.1,-24.3) 176(4.1,-24.6) 177(-4.1,-24.9) 178(4.1,-25.2) 179(-4.1,-25.5) 180(4.1,-25.8) 181(-4.1,-26.1) 182(4.1,-26.4) 183(-4.1,-26.7) 184(4.1,-27) 185(-4.1,-27.3) 186(4.1,-27.6) 187(-4.1,-27.9) 188(4.1,-28.2) 189(-4.1,-28.5) 190(4.1,-28.8) 191(-4.1,-29.1) 192(4.1,-29.4) 193(-4.1,-29.7) 194(4.1,-30) 195(-4.1,-30.3) 196(4.1,-30.6) 197(-4.1,-30.9) 198(4.1,-31.2) 199(-4.1,-31.5) 200(4.1,-31.8)
CAPC1005X56N
  rect 0.6x0.65 smd: 1(-0.5,0) 2(0.5,0)
CAPC1608X86N
  rect 0.95x1 smd: 1(-0.8,0) 2(0.8,0)
CAPC1608X87N
  rect 0.95x1 smd: 1(-0.8,0) 2(0.8,0)
CAPC2012X70N
  rect 1.15x1.45 smd: 1(-0.9,0) 2(0.9,0)
CAPC2012X71N
  rect 1.15x1.45 smd: 1(-0.9,0) 2(0.9,0)
CAPC2012X88N
  rect 1.15x1.45 smd: 1(-0.9,0) 2(0.9,0)
CAPC2012X100N
  rect 1.15x1.45 smd: 1(-0.9,0) 2(0.9,0)
CAPC2012X140N
  rect 1.15x1.45 smd: 1(-0.9,0) 2(0.9,0)
CAPMP3216X120N
  rect 1.8x1.25 smd: 1(-1.3,0) 2(1.3,0)
CAPMP3216X180N
  rect 1.8x1.25 smd: 1(-1.3,0) 2(1.3,0)
CAPMP6032X280N
  rect 2.35x2.25 smd: 1(-2.45,0) 2(2.45,0)
CAPMP7343X310N
  rect 2.35x2.45 smd: 1(-3.1,0) 2(3.1,0)
CAPMP7343X430N
  rect 2.35x2.45 smd: 1(-3.1,0) 2(3.1,0)
DRC10_2P4X1P65
  rect 0.85x0.28 smd: 1(-1.475,1) 2(-1.475,0.5) 3(-1.475,0) 4(-1.475,-0.5) 5(-1.475,-1) 6(1.475,-1) 7(1.475,-0.5) 8(1.475,0) 9(1.475,0.5) 10(1.475,1)
FT256
  round 0.45 smd: A1(-7.5,7.5) A2(-6.5,7.5) A3(-5.5,7.5) A4(-4.5,7.5) A5(-3.5,7.5) A6(-2.5,7.5) A7(-1.5,7.5) A8(-0.5,7.5) A9(0.5,7.5) A10(1.5,7.5) A11(2.5,7.5) A12(3.5,7.5) A13(4.5,7.5) A14(5.5,7.5) A15(6.5,7.5) A16(7.5,7.5) B1(-7.5,6.5) B2(-6.5,6.5) B3(-5.5,6.5) B4(-4.5,6.5) B5(-3.5,6.5) B6(-2.5,6.5) B7(-1.5,6.5) B8(-0.5,6.5) B9(0.5,6.5) B10(1.5,6.5) B11(2.5,6.5) B12(3.5,6.5) B13(4.5,6.5) B14(5.5,6.5) B15(6.5,6.5) B16(7.5,6.5) C1(-7.5,5.5) C2(-6.5,5.5) C3(-5.5,5.5) C4(-4.5,5.5) C5(-3.5,5.5) C6(-2.5,5.5) C7(-1.5,5.5) C8(-0.5,5.5) C9(0.5,5.5) C10(1.5,5.5) C11(2.5,5.5) C12(3.5,5.5) C13(4.5,5.5) C14(5.5,5.5) C15(6.5,5.5) C16(7.5,5.5) D1(-7.5,4.5) D2(-6.5,4.5) D3(-5.5,4.5) D4(-4.5,4.5) D5(-3.5,4.5) D6(-2.5,4.5) D7(-1.5,4.5) D8(-0.5,4.5) D9(0.5,4.5) D10(1.5,4.5) D11(2.5,4.5) D12(3.5,4.5) D13(4.5,4.5) D14(5.5,4.5) D15(6.5,4.5) D16(7.5,4.5) E1(-7.5,3.5) E2(-6.5,3.5) E3(-5.5,3.5) E4(-4.5,3.5) E5(-3.5,3.5) E6(-2.5,3.5) E7(-1.5,3.5) E8(-0.5,3.5) E9(0.5,3.5) E10(1.5,3.5) E11(2.5,3.5) E12(3.5,3.5) E13(4.5,3.5) E14(5.5,3.5) E15(6.5,3.5) E16(7.5,3.5) F1(-7.5,2.5) F2(-6.5,2.5) F3(-5.5,2.5) F4(-4.5,2.5) F5(-3.5,2.5) F6(-2.5,2.5) F7(-1.5,2.5) F8(-0.5,2.5) F9(0.5,2.5) F10(1.5,2.5) F11(2.5,2.5) F12(3.5,2.5) F13(4.5,2.5) F14(5.5,2.5) F15(6.5,2.5) F16(7.5,2.5) G1(-7.5,1.5) G2(-6.5,1.5) G3(-5.5,1.5) G4(-4.5,1.5) G5(-3.5,1.5) G6(-2.5,1.5) G7(-1.5,1.5) G8(-0.5,1.5) G9(0.5,1.5) G10(1.5,1.5) G11(2.5,1.5) G12(3.5,1.5) G13(4.5,1.5) G14(5.5,1.5) G15(6.5,1.5) G16(7.5,1.5) H1(-7.5,0.5) H2(-6.5,0.5) H3(-5.5,0.5) H4(-4.5,0.5) H5(-3.5,0.5) H6(-2.5,0.5) H7(-1.5,0.5) H8(-0.5,0.5) H9(0.5,0.5) H10(1.5,0.5) H11(2.5,0.5) H12(3.5,0.5) H13(4.5,0.5) H14(5.5,0.5) H15(6.5,0.5) H16(7.5,0.5) J1(-7.5,-0.5) J2(-6.5,-0.5) J3(-5.5,-0.5) J4(-4.5,-0.5) J5(-3.5,-0.5) J6(-2.5,-0.5) J7(-1.5,-0.5) J8(-0.5,-0.5) J9(0.5,-0.5) J10(1.5,-0.5) J11(2.5,-0.5) J12(3.5,-0.5) J13(4.5,-0.5) J14(5.5,-0.5) J15(6.5,-0.5) J16(7.5,-0.5) K1(-7.5,-1.5) K2(-6.5,-1.5) K3(-5.5,-1.5) K4(-4.5,-1.5) K5(-3.5,-1.5) K6(-2.5,-1.5) K7(-1.5,-1.5) K8(-0.5,-1.5) K9(0.5,-1.5) K10(1.5,-1.5) K11(2.5,-1.5) K12(3.5,-1.5) K13(4.5,-1.5) K14(5.5,-1.5) K15(6.5,-1.5) K16(7.5,-1.5) L1(-7.5,-2.5) L2(-6.5,-2.5) L3(-5.5,-2.5) L4(-4.5,-2.5) L5(-3.5,-2.5) L6(-2.5,-2.5) L7(-1.5,-2.5) L8(-0.5,-2.5) L9(0.5,-2.5) L10(1.5,-2.5) L11(2.5,-2.5) L12(3.5,-2.5) L13(4.5,-2.5) L14(5.5,-2.5) L15(6.5,-2.5) L16(7.5,-2.5) M1(-7.5,-3.5) M2(-6.5,-3.5) M3(-5.5,-3.5) M4(-4.5,-3.5) M5(-3.5,-3.5) M6(-2.5,-3.5) M7(-1.5,-3.5) M8(-0.5,-3.5) M9(0.5,-3.5) M10(1.5,-3.5) M11(2.5,-3.5) M12(3.5,-3.5) M13(4.5,-3.5) M14(5.5,-3.5) M15(6.5,-3.5) M16(7.5,-3.5) N1(-7.5,-4.5) N2(-6.5,-4.5) N3(-5.5,-4.5) N4(-4.5,-4.5) N5(-3.5,-4.5) N6(-2.5,-4.5) N7(-1.5,-4.5) N8(-0.5,-4.5) N9(0.5,-4.5) N10(1.5,-4.5) N11(2.5,-4.5) N12(3.5,-4.5) N13(4.5,-4.5) N14(5.5,-4.5) N15(6.5,-4.5) N16(7.5,-4.5) P1(-7.5,-5.5) P2(-6.5,-5.5) P3(-5.5,-5.5) P4(-4.5,-5.5) P5(-3.5,-5.5) P6(-2.5,-5.5) P7(-1.5,-5.5) P8(-0.5,-5.5) P9(0.5,-5.5) P10(1.5,-5.5) P11(2.5,-5.5) P12(3.5,-5.5) P13(4.5,-5.5) P14(5.5,-5.5) P15(6.5,-5.5) P16(7.5,-5.5) R1(-7.5,-6.5) R2(-6.5,-6.5) R3(-5.5,-6.5) R4(-4.5,-6.5) R5(-3.5,-6.5) R6(-2.5,-6.5) R7(-1.5,-6.5) R8(-0.5,-6.5) R9(0.5,-6.5) R10(1.5,-6.5) R11(2.5,-6.5) R12(3.5,-6.5) R13(4.5,-6.5) R14(5.5,-6.5) R15(6.5,-6.5) R16(7.5,-6.5) T1(-7.5,-7.5) T2(-6.5,-7.5) T3(-5.5,-7.5) T4(-4.5,-7.5) T5(-3.5,-7.5) T6(-2.5,-7.5) T7(-1.5,-7.5) T8(-0.5,-7.5) T9(0.5,-7.5) T10(1.5,-7.5) T11(2.5,-7.5) T12(3.5,-7.5) T13(4.5,-7.5) T14(5.5,-7.5) T15(6.5,-7.5) T16(7.5,-7.5)
IND_CENTRAL_1008
  rect 1.02x2.54 smd: 1(-1.145,0) 2(1.145,0)
INDC1005X60N
  rect 0.6x0.7 smd: 1(-0.5,0) 2(0.5,0)
INDC2520X220N
  rect 0.95x2.3 smd: 1(-1.25,0) 2(1.25,0)
LEDC2012X120N
  rect 1x1.4 smd: A(0.9,0) C(-0.9,0)
LTUMODULE7X11
  custom 0.159x0.159 smd: A1(-3.81,6.35)
  rect 0.635x0.635 smd: A2(-2.54,6.35) A3(-1.27,6.35) A4(0,6.35) A5(1.27,6.35) A6(2.54,6.35) A7(3.81,6.35) B1(-3.81,5.08) B2(-2.54,5.08) B3(-1.27,5.08) B4(0,5.08) B5(1.27,5.08) B6(2.54,5.08) B7(3.81,5.08) C1(-3.81,3.81) C2(-2.54,3.81) C3(-1.27,3.81) C4(0,3.81) C5(1.27,3.81) C6(2.54,3.81) C7(3.81,3.81) D1(-3.81,2.54) D2(-2.54,2.54) D3(-1.27,2.54) D4(0,2.54) D5(1.27,2.54) D6(2.54,2.54) D7(3.81,2.54) E1(-3.81,1.27) E2(-2.54,1.27) E3(-1.27,1.27) E4(0,1.27) E5(1.27,1.27) E6(2.54,1.27) E7(3.81,1.27) F1(-3.81,0) F2(-2.54,0) F3(-1.27,0) F4(0,0) F5(1.27,0) F6(2.54,0) F7(3.81,0) G1(-3.81,-1.27) G2(-2.54,-1.27) G3(-1.27,-1.27) G4(0,-1.27) G5(1.27,-1.27) G6(2.54,-1.27) G7(3.81,-1.27) H5(1.27,-2.54) H6(2.54,-2.54) H7(3.81,-2.54) J1(-3.81,-3.81) J2(-2.54,-3.81) J3(-1.27,-3.81) J5(1.27,-3.81) J6(2.54,-3.81) J7(3.81,-3.81) K1(-3.81,-5.08) K2(-2.54,-5.08) K3(-1.27,-5.08) K5(1.27,-5.08) K6(2.54,-5.08) K7(3.81,-5.08) L1(-3.81,-6.35) L2(-2.54,-6.35) L3(-1.27,-6.35) L5(1.27,-6.35) L6(2.54,-6.35) L7(3.81,-6.35)
MOLEX_53261-8_FITNAIL
  rect 2.1x3 smd: (-6.909,0) (6.9,0)
  rect 0.75x1.6 smd: 1(-4.35,2.9) 2(-3.1,2.9) 3(-1.85,2.9) 4(-0.6,2.9) 5(0.6,2.9) 6(1.85,2.9) 7(3.1,2.9) 8(4.35,2.9)
MT47H128M
  round 1 smd: (-4.85,-7.1) (4.85,7.1)
  round 0.45 smd: A1(-3.2,5.6) A2(-2.4,5.6) A3(-1.6,5.6) A7(1.6,5.6) A8(2.4,5.6) A9(3.2,5.6) B1(-3.2,4.8) B2(-2.4,4.8) B3(-1.6,4.8) B7(1.6,4.8) B8(2.4,4.8) B9(3.2,4.8) C1(-3.2,4) C2(-2.4,4) C3(-1.6,4) C7(1.6,4) C8(2.4,4) C9(3.2,4) D1(-3.2,3.2) D2(-2.4,3.2) D3(-1.6,3.2) D7(1.6,3.2) D8(2.4,3.2) D9(3.2,3.2) E1(-3.2,2.4) E2(-2.4,2.4) E3(-1.6,2.4) E7(1.6,2.4) E8(2.4,2.4) E9(3.2,2.4) F1(-3.2,1.6) F2(-2.4,1.6) F3(-1.6,1.6) F7(1.6,1.6) F8(2.4,1.6) F9(3.2,1.6) G1(-3.2,0.8) G2(-2.4,0.8) G3(-1.6,0.8) G7(1.6,0.8) G8(2.4,0.8) G9(3.2,0.8) H1(-3.2,0) H2(-2.4,0) H3(-1.6,0) H7(1.6,0) H8(2.4,0) H9(3.2,0) J1(-3.2,-0.8) J2(-2.4,-0.8) J3(-1.6,-0.8) J7(1.6,-0.8) J8(2.4,-0.8) J9(3.2,-0.8) K2(-2.4,-1.6) K3(-1.6,-1.6) K7(1.6,-1.6) K8(2.4,-1.6) K9(3.2,-1.6) L1(-3.2,-2.4) L2(-2.4,-2.4) L3(-1.6,-2.4) L7(1.6,-2.4) L8(2.4,-2.4) M2(-2.4,-3.2) M3(-1.6,-3.2) M7(1.6,-3.2) M8(2.4,-3.2) M9(3.2,-3.2) N1(-3.2,-4) N2(-2.4,-4) N3(-1.6,-4) N7(1.6,-4) N8(2.4,-4) P2(-2.4,-4.8) P3(-1.6,-4.8) P7(1.6,-4.8) P8(2.4,-4.8) P9(3.2,-4.8) R1(-3.2,-5.6) R2(-2.4,-5.6) R3(-1.6,-5.6) R7(1.6,-5.6) R8(2.4,-5.6)
OSCCC350X600X120N
  rect 1.45x1.95 smd: 1(-1.4,2.376) 2(-1.4,-2.374) 3(1.4,-2.374) 4(1.4,2.376)
OSCSC254P500X700X200-6N
  rect 1.95x1.6 smd: 1(-2.05,2.541) 2(-2.05,0.001) 3(-2.05,-2.539) 4(2.05,-2.539) 5(2.05,0.001) 6(2.05,2.541)
QFN50P500X500X100-33N
  rect 0.8x0.3 smd: 1(-2.475,1.75) 2(-2.475,1.25) 3(-2.475,0.75) 4(-2.475,0.25) 5(-2.475,-0.25) 6(-2.475,-0.75) 7(-2.475,-1.25) 8(-2.475,-1.75) 17(2.475,-1.75) 18(2.475,-1.25) 19(2.475,-0.75) 20(2.475,-0.25) 21(2.475,0.25) 22(2.475,0.75) 23(2.475,1.25) 24(2.475,1.75)
  rect 0.3x0.8 smd: 9(-1.75,-2.475) 10(-1.25,-2.475) 11(-0.75,-2.475) 12(-0.25,-2.475) 13(0.25,-2.475) 14(0.75,-2.475) 15(1.25,-2.475) 16(1.75,-2.475) 25(1.75,2.475) 26(1.25,2.475) 27(0.75,2.475) 28(0.25,2.475) 29(-0.25,2.475) 30(-0.75,2.475) 31(-1.25,2.475) 32(-1.75,2.475)
  rect 3.2x3.2 smd: 33(0,0)
RESC0603X26N
  rect 0.45x0.4 smd: 1(-0.35,0) 2(0.35,0)
RESC0603X30N
  rect 0.45x0.4 smd: 1(-0.35,0) 2(0.35,0)
RESC1608X50N
  rect 0.85x1 smd: 1(-0.75,0) 2(0.75,0)
RESC1608X55N
  rect 0.9x1 smd: 1(-0.8,0) 2(0.8,0)
RESC2012X50N
  rect 0.95x1.45 smd: 1(-1,0) 2(1,0)
RESC2012X60N
  rect 0.95x1.4 smd: 1(-1,0) 2(1,0)
RESC2012X70N
  rect 1.05x1.4 smd: 1(-0.95,0) 2(0.95,0)
RESC3225X70N
  rect 1.1x2.7 smd: 1(-1.5,0) 2(1.5,0)
RESNET_8
  rect 0.55x0.2 smd: 1(-0.4,0.6) 2(-0.4,0.2) 3(-0.4,-0.2) 4(-0.4,-0.6) 5(0.4,-0.6) 6(0.4,-0.2) 7(0.4,0.2) 8(0.4,0.6)
SAMTEC_TST-107-XX-X-D
  rect 1.6x1.6 hole 1: 1(0,0)
  round 1.6 hole 1: 2(0,2.54) 3(2.54,0) 4(2.54,2.54) 5(5.08,0) 6(5.08,2.54) 7(7.62,0) 8(7.62,2.54) 9(10.16,0) 10(10.16,2.54) 11(12.7,0) 12(12.7,2.54) 13(15.24,0) 14(15.24,2.54)
SMB_90
  round 1.8 hole 1.2: 1(0,0)
  round 2.3 hole 1.7: 2(-2.54,2.54) 3(2.54,2.54) 4(-2.54,-2.54) 5(2.54,-2.54)
SOG0508WG244L225
  rect 0.635x2.388 smd: 1(0,0)
  oval 0.635x2.388 smd: 2(1.27,0) 3(2.54,0) 4(3.81,0) 5(3.81,4.978) 6(2.54,4.978) 7(1.27,4.978) 8(0,4.978)
SOIC127P600X175-8N
  rect 1.55x0.6 smd: 1(-2.7,1.905) 2(-2.7,0.635) 3(-2.7,-0.635) 4(-2.7,-1.905) 5(2.7,-1.905) 6(2.7,-0.635) 7(2.7,0.635) 8(2.7,1.905)
SOIC127P1028X265-20N
  oval 1.75x0.6 smd: 1(-4.7,5.715) 2(-4.7,4.445) 3(-4.7,3.175) 4(-4.7,1.905) 5(-4.7,0.635) 6(-4.7,-0.635) 7(-4.7,-1.905) 8(-4.7,-3.175) 9(-4.7,-4.445) 10(-4.7,-5.715) 11(4.7,-5.715) 12(4.7,-4.445) 13(4.7,-3.175) 14(4.7,-1.905) 15(4.7,-0.635) 16(4.7,0.635) 17(4.7,1.905) 18(4.7,3.175) 19(4.7,4.445) 20(4.7,5.715)
SOIC127P1032X265-20AN
  oval 1.85x0.6 smd: 1(-4.75,5.715) 2(-4.75,4.445) 3(-4.75,3.175) 4(-4.75,1.905) 5(-4.75,0.635) 6(-4.75,-0.635) 7(-4.75,-1.905) 8(-4.75,-3.175) 9(-4.75,-4.445) 10(-4.75,-5.715) 11(4.75,-5.715) 12(4.75,-4.445) 13(4.75,-3.175) 14(4.75,-1.905) 15(4.75,-0.635) 16(4.75,0.635) 17(4.75,1.905) 18(4.75,3.175) 19(4.75,4.445) 20(4.75,5.715)
SOIC254P1077X800-8M
  oval 3.05x2 smd: 1(-4.6,3.81) 2(-4.6,1.27) 3(-4.6,-1.27) 4(-4.6,-3.81) 5(5.685,-3.81) 6(5.685,-1.27) 7(5.685,1.27) 8(5.685,3.81)
SOJ127P866X375-32N
  oval 2.45x0.65 smd: 1(-3.55,9.525) 2(-3.55,8.255) 3(-3.55,6.985) 4(-3.55,5.715) 5(-3.55,4.445) 6(-3.55,3.175) 7(-3.55,1.905) 8(-3.55,0.635) 9(-3.55,-0.635) 10(-3.55,-1.905) 11(-3.55,-3.175) 12(-3.55,-4.445) 13(-3.55,-5.715) 14(-3.55,-6.985) 15(-3.55,-8.255) 16(-3.55,-9.525) 17(3.55,-9.525) 18(3.55,-8.255) 19(3.55,-6.985) 20(3.55,-5.715) 21(3.55,-4.445) 22(3.55,-3.175) 23(3.55,-1.905) 24(3.55,-0.635) 25(3.55,0.635) 26(3.55,1.905) 27(3.55,3.175) 28(3.55,4.445) 29(3.55,5.715) 30(3.55,6.985) 31(3.55,8.255) 32(3.55,9.525)
SOP50P810X110-48N
  rect 1.45x0.3 smd: 1(-3.8,5.75) 2(-3.8,5.25) 3(-3.8,4.75) 4(-3.8,4.25) 5(-3.8,3.75) 6(-3.8,3.25) 7(-3.8,2.75) 8(-3.8,2.25) 9(-3.8,1.75) 10(-3.8,1.25) 11(-3.8,0.75) 12(-3.8,0.25) 13(-3.8,-0.25) 14(-3.8,-0.75) 15(-3.8,-1.25) 16(-3.8,-1.75) 17(-3.8,-2.25) 18(-3.8,-2.75) 19(-3.8,-3.25) 20(-3.8,-3.75) 21(-3.8,-4.25) 22(-3.8,-4.75) 23(-3.8,-5.25) 24(-3.8,-5.75) 25(3.8,-5.75) 26(3.8,-5.25) 27(3.8,-4.75) 28(3.8,-4.25) 29(3.8,-3.75) 30(3.8,-3.25) 31(3.8,-2.75) 32(3.8,-2.25) 33(3.8,-1.75) 34(3.8,-1.25) 35(3.8,-0.75) 36(3.8,-0.25) 37(3.8,0.25) 38(3.8,0.75) 39(3.8,1.25) 40(3.8,1.75) 41(3.8,2.25) 42(3.8,2.75) 43(3.8,3.25) 44(3.8,3.75) 45(3.8,4.25) 46(3.8,4.75) 47(3.8,5.25) 48(3.8,5.75)
SOP65P780X200-28N
  rect 1.75x0.45 smd: 1(-3.6,4.225) 2(-3.6,3.575) 3(-3.6,2.925) 4(-3.6,2.275) 5(-3.6,1.625) 6(-3.6,0.975) 7(-3.6,0.325) 8(-3.6,-0.325) 9(-3.6,-0.975) 10(-3.6,-1.625) 11(-3.6,-2.275) 12(-3.6,-2.925) 13(-3.6,-3.575) 14(-3.6,-4.225) 15(3.6,-4.225) 16(3.6,-3.575) 17(3.6,-2.925) 18(3.6,-2.275) 19(3.6,-1.625) 20(3.6,-0.975) 21(3.6,-0.325) 22(3.6,0.325) 23(3.6,0.975) 24(3.6,1.625) 25(3.6,2.275) 26(3.6,2.925) 27(3.6,3.575) 28(3.6,4.225)
SOT95P230X109-3N
  rect 0.95x0.6 smd: 1(-1.15,0.95) 2(-1.15,-0.95) 3(1.15,0)
SOT95P240X114-3N
  rect 0.95x0.6 smd: 1(-1.15,0.95) 2(-1.15,-0.95) 3(1.15,0)
SOT343N
  rect 1.1x0.45 smd: 1(-0.9,0.65) 3(0.9,-0.65) 4(0.9,0.65)
  rect 1.1x0.8 smd: 2(-0.9,-0.5)
SW_EVQ-PH_NO_GND
  rect 1x3.2 smd: 1(-2,3.4) 2(2,3.4) 3(-2,-3.4) 4(2,-3.4)
TO92
  oval 2x1 hole 0.8: 1(0,0) 2(0,-1.27) 3(0,-2.54)
TO99
  round 1.575 hole 1: 1(0,0) 2(1.803,0.737) 3(2.54,2.54) 4(1.803,4.343) 5(0,5.08) 6(-1.803,4.343) 7(-2.54,2.54) 8(-1.803,0.737)
TO230P950X240-3N
  rect 2.3x0.95 smd: 1(-4.1,2.3) 2(-4.1,-2.3)
  rect 6.9x5.55 smd: 3(1.8,0)
TO254P1410X464-4N
  rect 3x1.05 smd: 1(-6,2.54) 2(-6,0) 3(-6,-2.54)
  rect 6.9x10.5 smd: 4(4.1,0)
TOROID01_3
  round 1.397 hole 0.8: 1(0,0) 2(2.54,0) 3(5.08,0)
unnamed#2
  round 1.397 hole 0.8: (13.462,8.382) (44.45,19.05) (50.546,6.604)
unnamed#3
  round 0.635 hole 3.175 unplated: (0,0)
USB3A_FEMALE
  round 1.1 hole 0.8: 1(-3.5,-1.5) 2(-1,-1.5) 3(1,-1.5) 4(3.5,-1.5) 5(4,0) 6(2,0) 7(0,0) 8(-2,0) 9(-4,0)
  round 2.9 hole 2.3: 10(-6.57,-3.5) 11(6.57,-3.5)
XCF01SVOG20
  rect 1.5x0.45 smd: 1(-2.9,2.925) 2(-2.9,2.275) 3(-2.9,1.625) 4(-2.9,0.975) 5(-2.9,0.325) 6(-2.9,-0.325) 7(-2.9,-0.975) 8(-2.9,-1.625) 9(-2.9,-2.275) 10(-2.9,-2.925) 11(2.9,-2.925) 12(2.9,-2.275) 13(2.9,-1.625) 14(2.9,-0.975) 15(2.9,-0.325) 16(2.9,0.325) 17(2.9,0.975) 18(2.9,1.625) 19(2.9,2.275) 20(2.9,2.925)

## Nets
0V9: C2011.1 C2012.1 C2013.1 P1.2 U12.J2 U13.J2 U51.3 U51.5(VOSNS)
1V2: C63.1 C125.1 C126.1 C127.1 C128.1 C129.1 C130.1 C131.1 C132.1 C133.1 C178.1 C179.1 C180.1 C181.1 C182.1 C183.1 C184.1 C185.1 C186.1 P1.4 U1.G7 U1.G9 U1.H8 U1.H10 U1.J7 U1.J9 U1.K8 U1.K10 U2.G7 U2.G9 U2.H8 U2.H10 U2.J7 U2.J9 U2.K8 U2.K10 U29.A1 U29.A2 U29.A3 U29.A4 U29.B1 U29.B2 U29.B3 U29.B4 U29.C1 U29.C2 U29.C3 U29.C4 U29.D1 U29.D2 U29.D3 U29.D4(VOUT#D4)
1V8: C73.1 C74.1 C75.1 C76.1 C77.1 C78.1 C79.1 C80.1 C81.1 C82.1 C83.1 C84.1 C85.1 C86.1 C87.1 C88.1 C105.1 C106.1 C134.1 C135.1 C136.1 C137.1 C138.1 C139.1 C140.1 C141.1 C142.1 C143.1 C187.1 C188.1 C189.1 C190.1 C191.1 C192.1 C193.1 C194.1 C195.1 C196.1 C2014.1 C2015.1 P1.6 R2010.1 U2.B4 U2.B9 U2.B13 U2.D2 U2.G4 U2.J2 U2.K4 U2.N2(VCCO_3#N2) U2.N7 U2.N15 U2.R13 U12.A1 U12.A9 U12.C1 U12.C3 U12.C7 U12.C9 U12.E1 U12.E9 U12.G1 U12.G7 U12.G9 U12.J1 U12.J9 U12.M9 U12.R1 U13.A1 U13.A9 U13.C1 U13.C3 U13.C7 U13.C9 U13.E1 U13.E9 U13.G1 U13.G7 U13.G9 U13.J1 U13.J9 U13.M9 U13.R1 U51.2
2V5: C65.1 C89.1 C90.1 C91.1 C92.1 C93.1 C94.1 C95.1 C96.1 C97.1 C98.1 C99.1 C100.1 C101.1 C102.1 C103.1 C104.1 C116.1 C117.1 C118.1 C119.1 C120.1 C121.1 C122.1 C123.1 C124.1 C144.1 C145.1 C146.1 C147.1 C148.1 C149.1 C150.1 C151.1 C152.1 C153.1 C154.1 C155.1 C156.1 C157.1 C158.1 C159.1 C169.1 C170.1 C171.1 C172.1 C173.1 C174.1 C175.1 C176.1 C177.1 P1.14 U1.D2 U1.E5 U1.F8 U1.F11 U1.G4 U1.G10 U1.H6 U1.J2 U1.J10 U1.K4 U1.L6 U1.L9 U1.N2(VCCO_3#N2) U1.N7 U1.N10 U1.R4 U1.R8 U1.R13 U2.D7 U2.D10 U2.D15 U2.E5 U2.F8 U2.F11 U2.G10 U2.H6 U2.J10 U2.L6 U2.L9 U2.N10 U2.R4 U2.R8 U10.19(VCCO) U10.20 U11.19(VCCO) U11.20 U30.A1 U30.A2 U30.A3 U30.A4 U30.B1 U30.B2 U30.B3 U30.B4 U30.C1 U30.C2 U30.C3 U30.C4 U30.D1 U30.D2 U30.D3 U30.D4(VOUT#D4)
3V3: C67.1 C107.1 C108.1 C109.1 C110.1 C111.1 C112.1 C113.1 C114.1 C115.1 C160.1 C161.1 C162.1 C163.1 C164.1 C165.1 C166.1 C167.1 C168.1 P1.12 R2012.1 RN1.5(2) RN1.6 RN1.7 RN1.8 U1.B4 U1.B9 U1.B13 U1.D7 U1.D10 U1.D15 U1.G13 U1.J15 U1.K13 U1.N15 U2.G13 U2.J15 U2.K13 U10.18 U11.18 U29.H5 U30.H5 U31.A1 U31.A2 U31.A3 U31.A4 U31.B1 U31.B2 U31.B3 U31.B4 U31.C1 U31.C2 U31.C3 U31.C4 U31.D1 U31.D2 U31.D3 U31.D4(VOUT#D4) U51.7 U51.10
5V: C23.1 C24.1 C25.1 C26.1 C27.1 C28.1 C29.1 C30.1 U4.6(DVDD#6) U4.11 U4.18 U4.23 U5.3 XTAL1.1 XTAL1.2 XTAL1.6(VCC)
GND EARTH: C1.2 C2.2 J1.2 J1.3 J1.4 J1.5(SHIELD3) J2.2 J2.3 J2.4 J2.5(SHIELD3) J3.2 J3.3 J3.4 J3.5(SHIELD3) SW1.5(B4) SW1.6 SW1.7 SW1.8
V12N: J6.A3 J6.A4 J6.D3 J6.D4 U33.7 U34.4(VMIN) U36.7 U37.4(VMIN)
VCC: C44.1 C45.1 C46.1 C47.1 C48.1 C49.1 C50.1 C51.1 C52.1 C53.1 C54.1 C55.1 C197.1 C200.1 C2006.1 C2007.2 J5.1(VBUS) J6.A23 J6.A24 J6.D23 J6.D24 J7.31 J7.32 J7.33 J7.34 J7.35 J7.36 J7.37 J7.38 J7.81 J7.82 J7.83 J7.84 J7.85 J7.86 J7.87 J7.88 J7.131 J7.132 J7.133 J7.134 J7.135 J7.136 J7.137 J7.138 J7.181 J7.182 J7.183 J7.184 J7.185 J7.186 J7.187 J7.188 L8.1 L10.1 R27.1 R28.1 R29.1 R30.1 R2006.1 R2007.2 R2008.1 U6.7 U6.18 U6.31 U6.42 U7.20(VCC) U8.7 U8.18 U8.31 U8.42 U9.7 U9.18 U9.31 U9.42 U22.20(VCC) U32.2 U32.9(VD2) U35.2 U35.9(VD2) U38.20(VCC) U39.20(VCC) U40.32 U41.32 U42.32 U43.32 U44.32 U45.32 U46.32 U47.32 U48.20(VCC) U49.4(VCC) U50.27 U50.28 U50.32
0: C3.2 C4.2 C5.2 C6.2 C7.2 C8.2 C9.2 C10.2 C12.1 C13.1 C14.1 C15.1 C16.1 C23.2 C24.2 C25.2 C26.2 C27.2 C28.2 C29.2 C30.2 C31.1 C32.1 C33.1 C36.1 C37.1 C38.2 C39.1 C40.1 C44.2 C45.2 C46.2 C47.2 C48.2 C49.2 C50.2 C51.2 C52.2 C53.2 C54.2 C55.2 C62.2 C63.2 C64.2 C65.2 C66.2 C67.2 C68.1 C72.1 C73.2 C74.2 C75.2 C76.2 C77.2 C78.2 C79.2 C80.2 C81.2 C82.2 C83.2 C84.2 C85.2 C86.2 C87.2 C88.2 C89.2 C90.2 C91.2 C92.2 C93.2 C94.2 C95.2 C96.2 C97.2 C98.2 C99.2 C100.2 C101.2 C102.2 C103.2 C104.2 C105.2 C106.2 C107.2 C108.2 C109.2 C110.2 C111.2 C112.2 C113.2 C114.2 C115.2 C116.2 C117.2 C118.2 C119.2 C120.2 C121.2 C122.2 C123.2 C124.2 C125.2 C126.2 C127.2 C128.2 C129.2 C130.2 C131.2 C132.2 C133.2 C134.2 C135.2 C136.2 C137.2 C138.2 C139.2 C140.2 C141.2 C142.2 C143.2 C144.2 C145.2 C146.2 C147.2 C148.2 C149.2 C150.2 C151.2 C152.2 C153.2 C154.2 C155.2 C156.2 C157.2 C158.2 C159.2 C160.2 C161.2 C162.2 C163.2 C164.2 C165.2 C166.2 C167.2 C168.2 C169.2 C170.2 C171.2 C172.2 C173.2 C174.2 C175.2 C176.2 C177.2 C178.2 C179.2 C180.2 C181.2 C182.2 C183.2 C184.2 C185.2 C186.2 C187.2 C188.2 C189.2 C190.2 C191.2 C192.2 C193.2 C194.2 C195.2 C196.2 C197.2 C198.2 C199.2 C200.2 C201.2 C202.2 C2000.2 C2001.2 C2002.2 C2003.2 C2004.2 C2005.2 C2006.2 C2007.1 C2008.2 C2009.2 C2010.2 C2011.2 C2012.2 C2013.2 C2014.2 C2015.2 C2016.2 J5.4 J5.7 J6.C1 J6.C2 J6.C23 J6.C24 J6.F1 J6.F2 J6.F23 J6.F24 J7.39 J7.40 J7.41 J7.42 J7.43 J7.44 J7.45 J7.46 J7.47 J7.48 J7.49 J7.50 J7.89 J7.90 J7.91 J7.92 J7.93 J7.94 J7.95 J7.96 J7.97 J7.98 J7.99 J7.100 J7.139 J7.140 J7.141 J7.142 J7.143 J7.144 J7.145 J7.146 J7.147 J7.148 J7.149 J7.150 J7.189 J7.190 J7.191 J7.192 J7.193 J7.194 J7.195 J7.196 J7.197 J7.198 J7.199 J7.200(PIN200) P1.1 P1.5 P1.9(PIN9) P1.13 Q4.2(E) Q5.2(E) Q6.2(E) Q7.2(E) R12.1 R14.1 R18.1 R23.1 R24.1 R25.1 R39.2 R40.2 R41.2 R42.2 R43.2 R44.2 R51.2 R52.1 R2011.2 SW2.1 U1.A1 U1.A16 U1.B7 U1.B11 U1.D4 U1.D13 U1.E9 U1.G2 U1.G8 U1.G15 U1.H7 U1.H9 U1.H12 U1.J5 U1.J8 U1.K7 U1.K9 U1.L2 U1.L15 U1.M8 U1.N13 U1.P3 U1.R6 U1.R10 U1.T1 U1.T16 U2.A1 U2.A16 U2.B7 U2.B11 U2.D4 U2.D13 U2.E9 U2.G2 U2.G8 U2.G15 U2.H7 U2.H9 U2.H12 U2.J5 U2.J8 U2.K7 U2.K9 U2.L2 U2.L15 U2.M8 U2.N13 U2.P3 U2.R6 U2.R10 U2.T1 U2.T16 U3.2 U3.3 U3.6 U3.7 U4.5 U4.10 U4.19 U4.24 U5.2 U5.4(TGND) U6.4 U6.10 U6.15 U6.21 U6.24 U6.25(G\) U6.28 U6.34 U6.39 U6.45 U7.10 U8.1 U8.4 U8.10 U8.15 U8.21 U8.28 U8.34 U8.39 U8.45 U8.48 U9.4 U9.10 U9.15 U9.21 U9.24 U9.25(G\) U9.28 U9.34 U9.39 U9.45 U10.11 U11.11 U12.A3 U12.A7 U12.B2 U12.B8 U12.D2 U12.D8 U12.E3 U12.E7 U12.F2 U12.F8 U12.H2 U12.H8(VSSQ#H8) U12.J3 U12.J7 U12.N1 U12.P9 U13.A3 U13.A7 U13.B2 U13.B8 U13.D2 U13.D8 U13.E3 U13.E7 U13.F2 U13.F8 U13.H2 U13.H8(VSSQ#H8) U13.J3 U13.J7 U13.N1 U13.P9 U22.1 U22.10 U29.A5 U29.A6 U29.A7 U29.B5 U29.B6 U29.B7 U29.C5 U29.C6 U29.C7 U29.D5 U29.D6 U29.D7 U29.E1 U29.E2 U29.E3 U29.E4 U29.E5 U29.E6 U29.E7 U29.F1 U29.F2 U29.F3 U29.F4 U29.F5 U29.F6 U29.F7 U29.G1 U29.G2 U29.G3 U29.G4 U29.G6 U29.H6 U29.J5 U29.J6 U29.K5 U29.K6 U29.L6 U29.L7 U30.A5 U30.A6 U30.A7 U30.B5 U30.B6 U30.B7 U30.C5 U30.C6 U30.C7 U30.D5 U30.D6 U30.D7 U30.E1 U30.E2 U30.E3 U30.E4 U30.E5 U30.E6 U30.E7 U30.F1 U30.F2 U30.F3 U30.F4 U30.F5 U30.F6 U30.F7 U30.G1 U30.G2 U30.G3 U30.G4 U30.G6 U30.H6 U30.J5 U30.J6 U30.K5 U30.K6 U30.L6 U30.L7 U31.A5 U31.A6 U31.A7 U31.B5 U31.B6 U31.B7 U31.C5 U31.C6 U31.C7 U31.D5 U31.D6 U31.D7 U31.E1 U31.E2 U31.E3 U31.E4 U31.E5 U31.E6 U31.E7 U31.F1 U31.F2 U31.F3 U31.F4 U31.F5 U31.F6 U31.F7 U31.G1 U31.G2 U31.G3 U31.G4 U31.G6 U31.H6 U31.J5 U31.J6 U31.K5 U31.K6 U31.L6 U31.L7 U32.1 U32.3 U32.7 U32.10 U32.20 U33.3 U35.1 U35.3 U35.7 U35.10 U35.20 U36.3 U38.1 U38.10 U39.1 U39.10 U40.16 U40.24 U41.16 U41.24 U42.16 U42.24 U43.16 U43.24 U44.16 U44.24 U45.16 U45.24 U46.16 U46.24 U47.16 U47.24 U48.10 U49.1 U50.1 U50.2 U50.3 U50.12 U50.13 U50.14 U50.15 U50.17 U50.18 U50.20 U50.22 U50.23 U50.25 U50.29 U50.33 U51.4 U51.8
A0: J6.B8 U9.36
A1: J6.B7 U9.35
A2: J6.B6 U9.33
A3: J6.B5 U9.32
A4: J6.B4 U9.30
A5: J6.B3 U9.29
A6: J6.B2 U9.27
A7: J6.B1 U9.26
A8: J6.B16 U8.47
A9: J6.B15 U8.46
A10: J6.B14 U8.44
A11: J6.B13 U8.43
A12: J6.B12 U8.41
A13: J6.B11 U8.40
A14: J6.B10 U8.38
A15: J6.B9 U8.37
A16: J6.B24 U6.36
A17: J6.B23 U6.35
A18: J6.B22 U6.33 U7.6
A19: J6.B21 U6.32 U7.5
A20: J6.B20 U6.30 U7.4
A21: J6.B19 U6.29 U7.3
A22: J6.B18 U6.27 U7.2
A23: J6.B17 U6.26
AEN/: J6.E3 U7.7
BRD/: U7.13 U48.7
BRESET: U7.12 U48.8
BUF_OUT: C41.2 R50.1
BWR/: U7.14 U48.6
CENTER-TAP: C41.1 R21.2
CLKC: R26.1 U1.C3
CLOCK+: U1.H4 U2.J11 U50.31
CLOCK-: U1.H3 U2.J12 U50.30
CONF_SW0: RN1.1 SW1.1 U1.T11
CONF_SW1: RN1.2 SW1.2 U1.R11
CONF_SW2: RN1.3 SW1.3 U1.N8
CONF_SW3: RN1.4 SW1.4 U1.M9
D0: J6.E8 U8.26 U9.37
D1: J6.E9 U8.27 U9.38
D2: J6.E10 U8.29 U9.40
D3: J6.E11 U8.30 U9.41
D4: J6.E12 U8.32 U9.43
D5: J6.E13 U8.33 U9.44
D6: J6.E14 U8.35 U9.46
D7: J6.E15 U8.36 U9.47
D8: J6.E24 U6.47
D9: J6.E23 U6.46
D10: J6.E22 U6.44
D11: J6.E21 U6.43
D12: J6.E20 U6.41
D13: J6.E19 U6.40
D14: J6.E18 U6.38
D15: J6.E17 U6.37
D+: C2001.1 R2000.2 U2.N11
D-: C2000.1 R2001.2 U2.P11
DATA0+: U1.B6 U2.B5
DATA0-: U1.A6 U2.A5
DATA1+: U1.D6 U2.D5
DATA1-: U1.C6 U2.C5
DATA1.CLKA: U1.K5 U32.11 U35.11 U38.11
DATA1.VD0: RN3.1 U1.M2
DATA1.VD1: RN3.2 U1.M1
DATA1.VD2: RN3.3 U1.N3
